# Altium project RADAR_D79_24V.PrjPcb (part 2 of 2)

## Sheet 23_Radar_bypass.SchDoc
size 289 x 400 mm
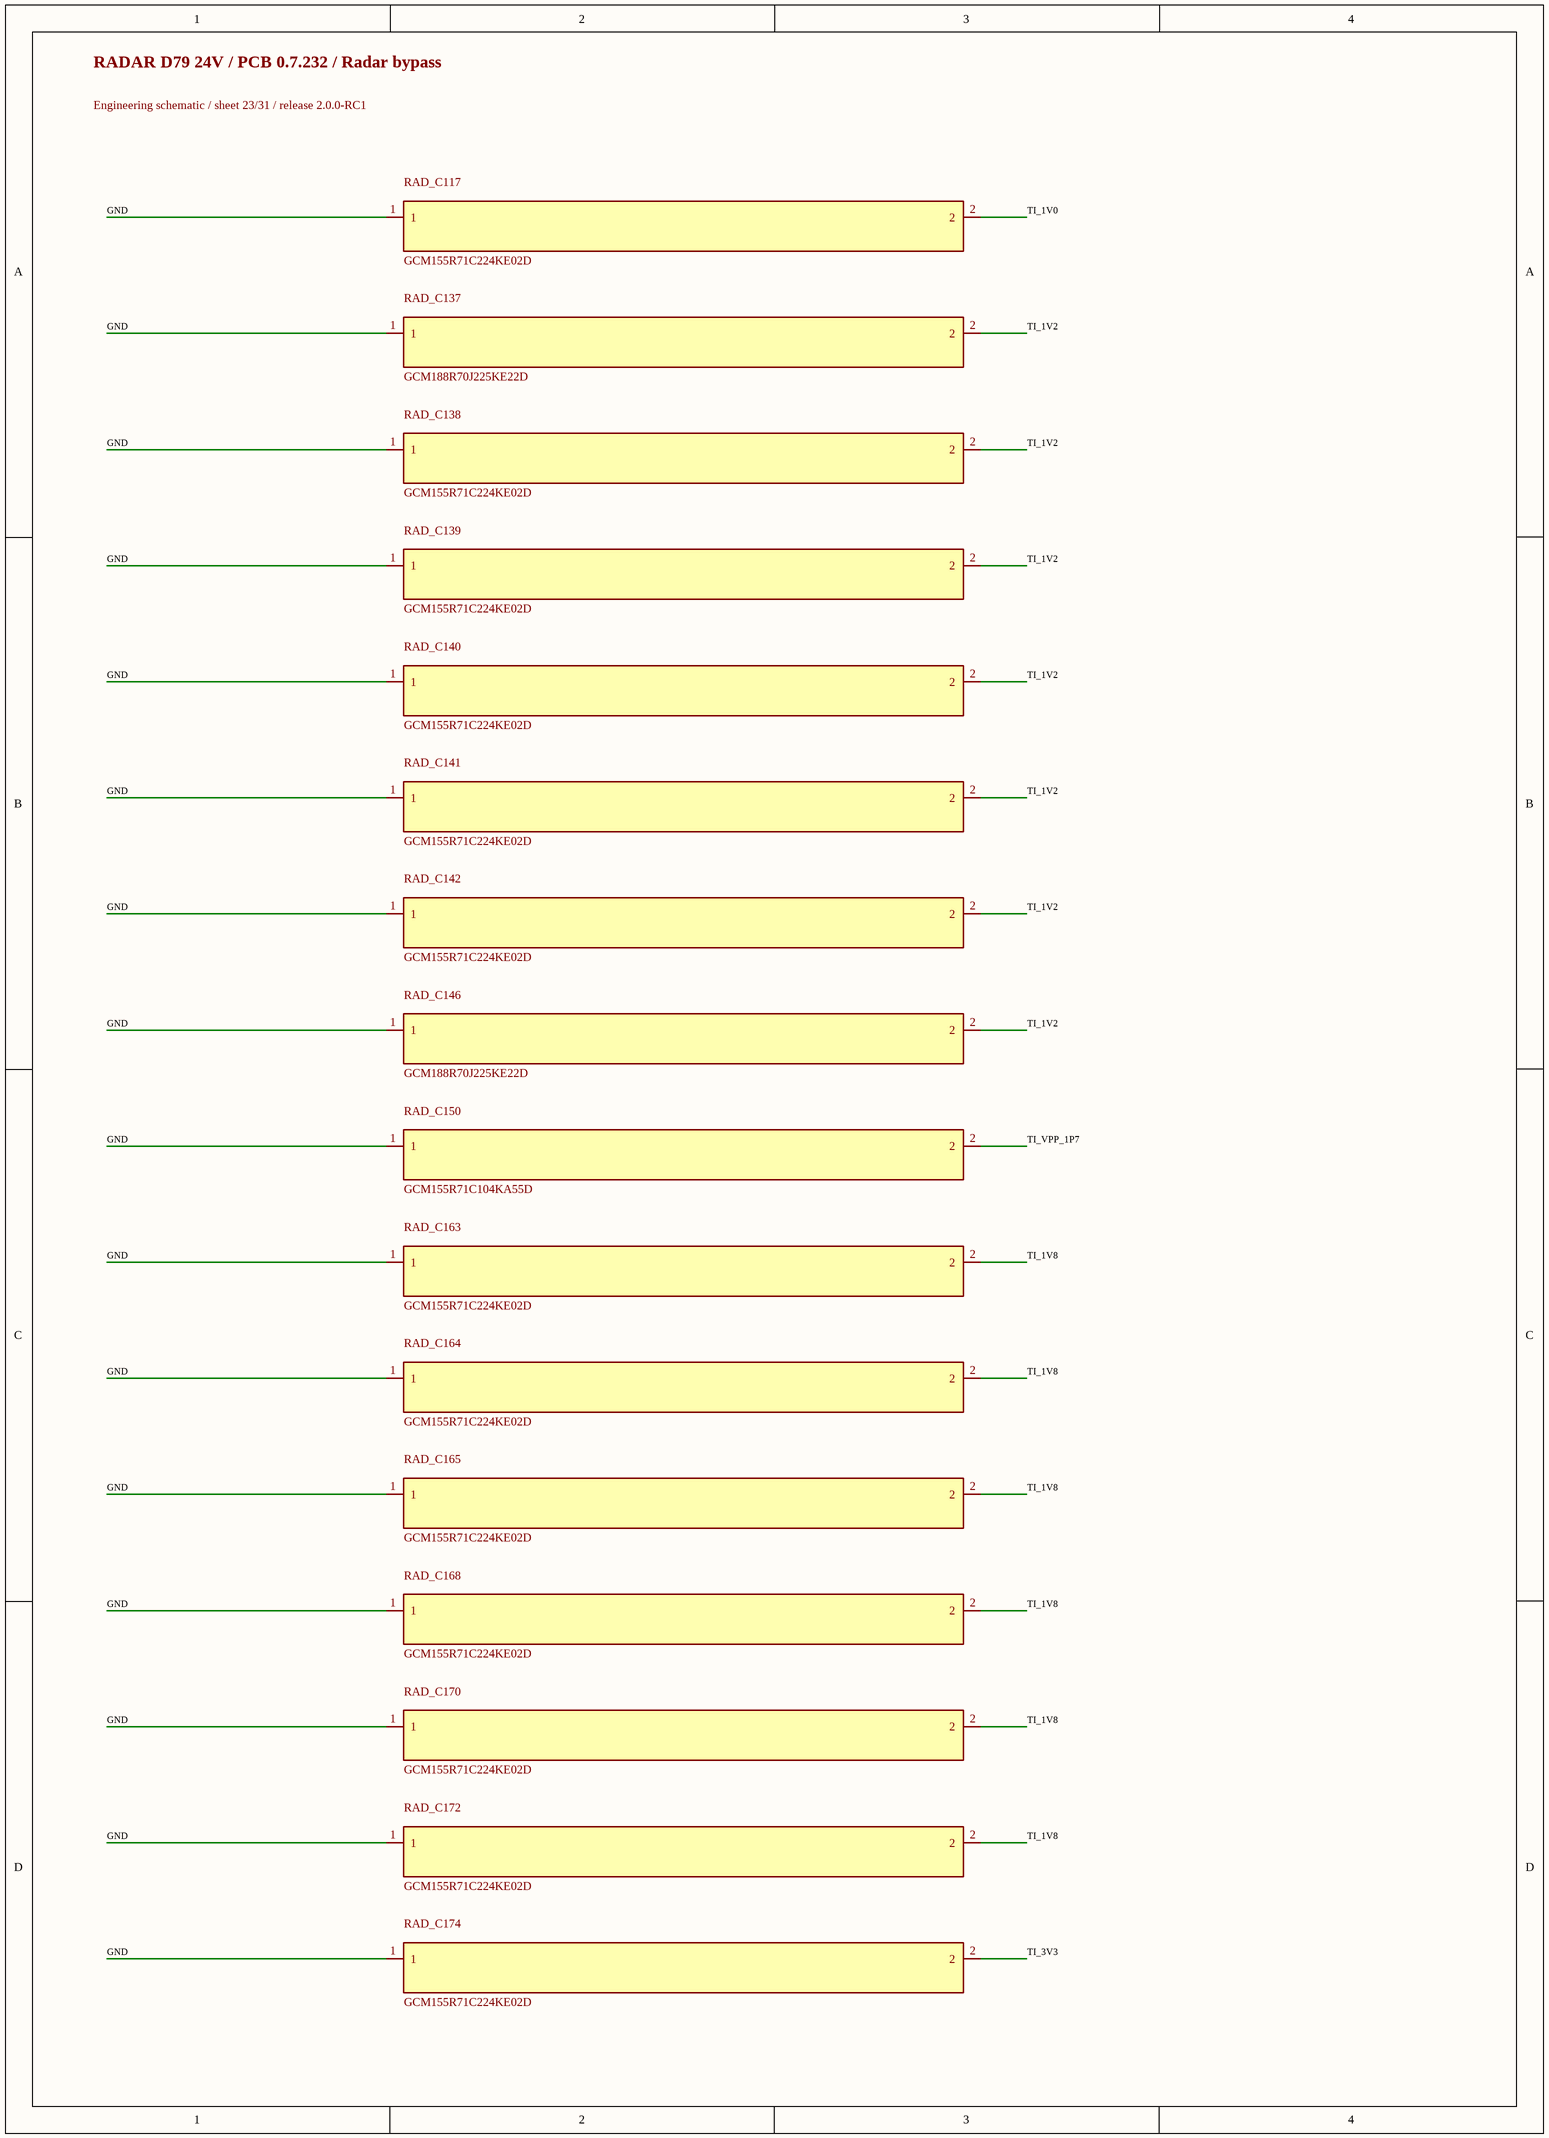
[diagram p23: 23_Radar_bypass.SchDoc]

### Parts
RAD_C117  GCM155R71C224KE02D  [0402L]
RAD_C137  GCM188R70J225KE22D  [0603L]
RAD_C138  GCM155R71C224KE02D  [0402L]
RAD_C139  GCM155R71C224KE02D  [0402L]
RAD_C140  GCM155R71C224KE02D  [0402L]
RAD_C141  GCM155R71C224KE02D  [0402L]
RAD_C142  GCM155R71C224KE02D  [0402L]
RAD_C146  GCM188R70J225KE22D  [0603L]
RAD_C150  GCM155R71C104KA55D  [0402L]
RAD_C163  GCM155R71C224KE02D  [0402L]
RAD_C164  GCM155R71C224KE02D  [0402L]
RAD_C165  GCM155R71C224KE02D  [0402L]
RAD_C168  GCM155R71C224KE02D  [0402L]
RAD_C170  GCM155R71C224KE02D  [0402L]
RAD_C172  GCM155R71C224KE02D  [0402L]
RAD_C174  GCM155R71C224KE02D  [0402L]

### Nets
GND: RAD_C117.1 RAD_C137.1 RAD_C138.1 RAD_C139.1 RAD_C140.1 RAD_C141.1 RAD_C142.1 RAD_C146.1 RAD_C150.1 RAD_C163.1 RAD_C164.1 RAD_C165.1 RAD_C168.1 RAD_C170.1 RAD_C172.1 RAD_C174.1
TI_1V0: RAD_C117.2
TI_1V2: RAD_C137.2 RAD_C138.2 RAD_C139.2 RAD_C140.2 RAD_C141.2 RAD_C142.2 RAD_C146.2
TI_1V8: RAD_C163.2 RAD_C164.2 RAD_C165.2 RAD_C168.2 RAD_C170.2 RAD_C172.2
TI_3V3: RAD_C174.2
TI_VPP_1P7: RAD_C150.2

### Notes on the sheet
- RADAR D79 24V / PCB 0.7.232 / Radar bypass
- Engineering schematic / sheet 23/31 / release 2.0.0-RC1

## Sheet 24_Radar_bypass.SchDoc
size 289 x 396 mm
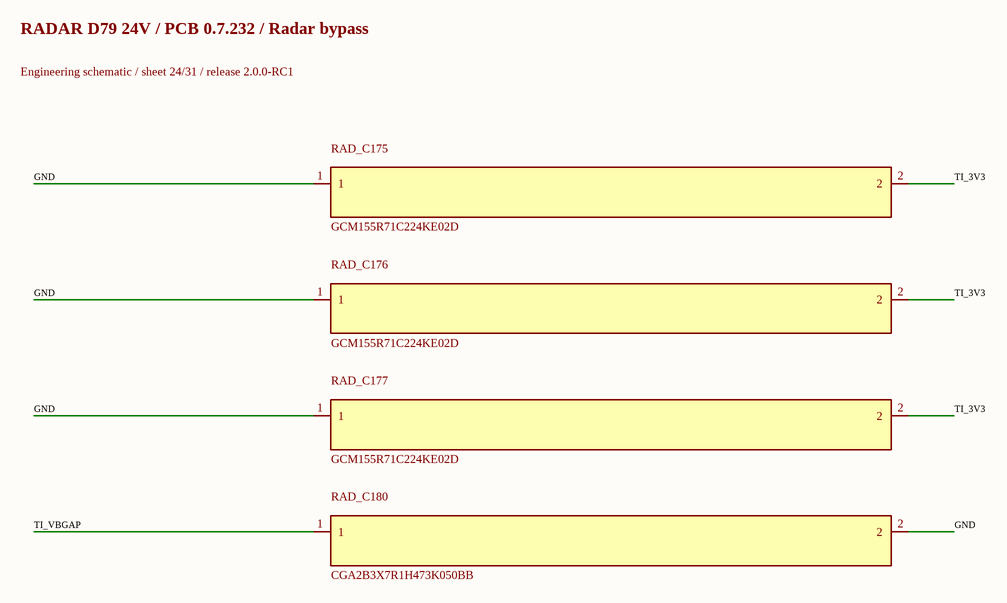
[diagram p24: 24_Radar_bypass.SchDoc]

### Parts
RAD_C175  GCM155R71C224KE02D  [0402L]
RAD_C176  GCM155R71C224KE02D  [0402L]
RAD_C177  GCM155R71C224KE02D  [0402L]
RAD_C180  CGA2B3X7R1H473K050BB  [0402L]

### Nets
GND: RAD_C175.1 RAD_C176.1 RAD_C177.1 RAD_C180.2
TI_3V3: RAD_C175.2 RAD_C176.2 RAD_C177.2
TI_VBGAP: RAD_C180.1

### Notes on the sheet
- RADAR D79 24V / PCB 0.7.232 / Radar bypass
- Engineering schematic / sheet 24/31 / release 2.0.0-RC1

## Sheet 25_Radar_PMIC_and_rail_filters.SchDoc
size 289 x 396 mm
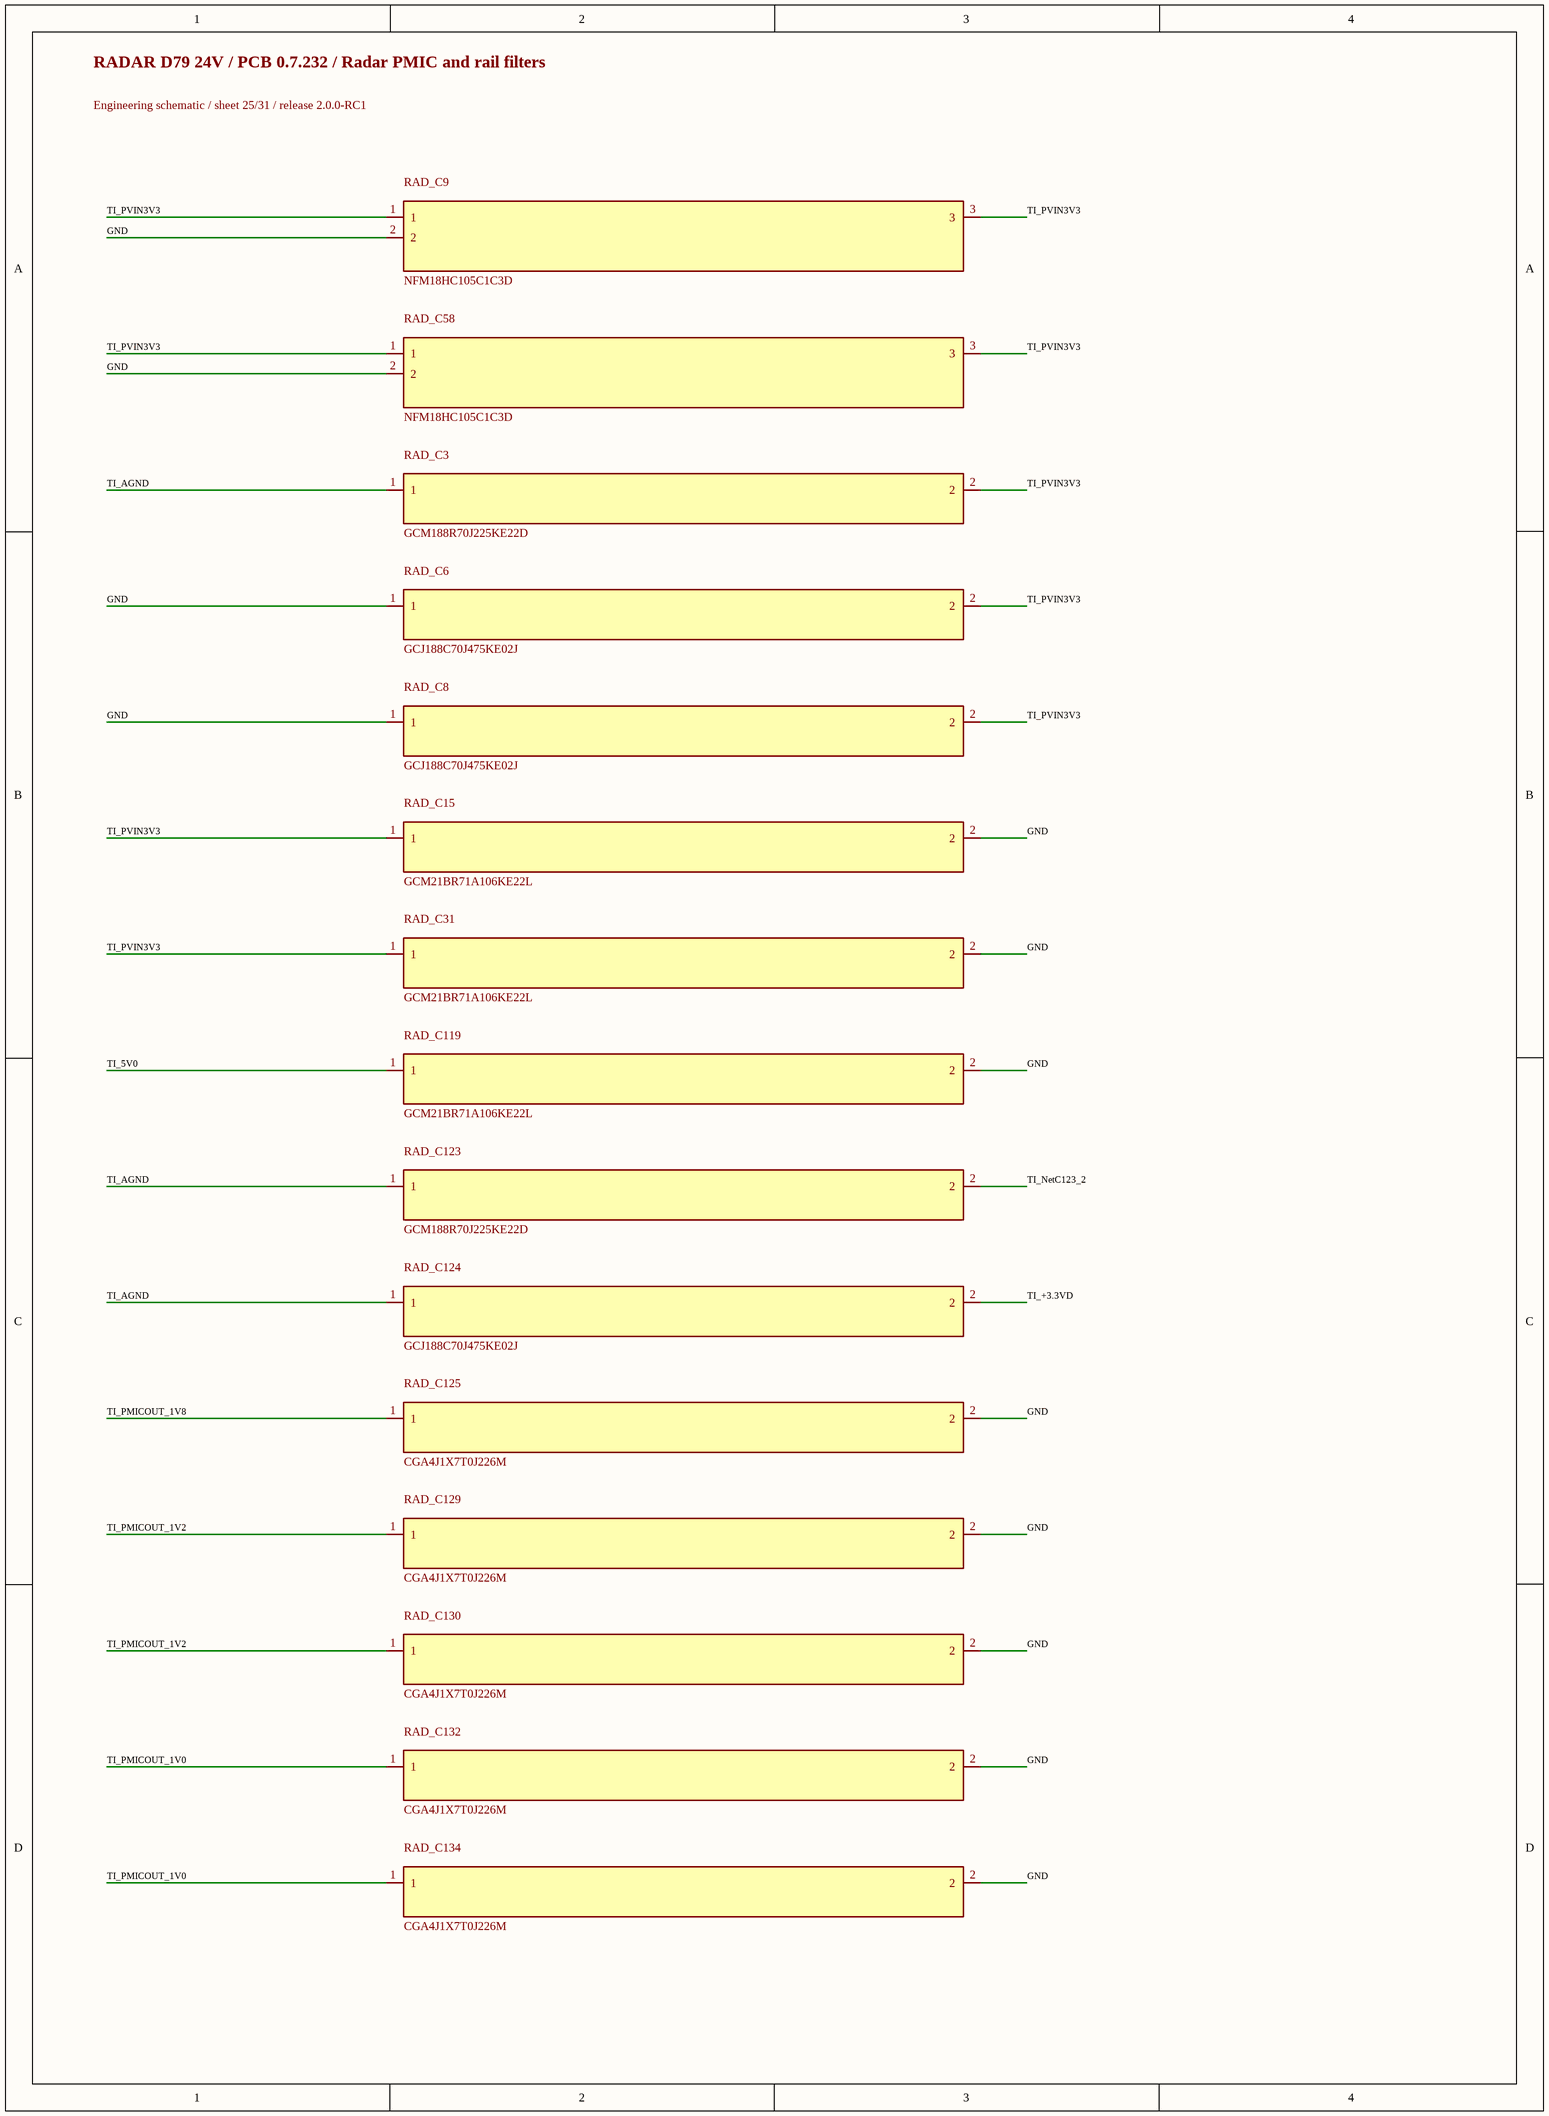
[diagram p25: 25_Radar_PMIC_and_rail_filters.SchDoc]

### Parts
RAD_C3  GCM188R70J225KE22D  [0603L]
RAD_C6  GCJ188C70J475KE02J  [FP-GCJ188C70J475KE02J_0603-MFG]
RAD_C8  GCJ188C70J475KE02J  [FP-GCJ188C70J475KE02J_0603-MFG]
RAD_C9  NFM18HC105C1C3D  [FP-NFM18HC105C1C3D_0603-MFG]
RAD_C15  GCM21BR71A106KE22L  [0805L]
RAD_C31  GCM21BR71A106KE22L  [0805L]
RAD_C58  NFM18HC105C1C3D  [FP-NFM18HC105C1C3D_0603-MFG]
RAD_C119  GCM21BR71A106KE22L  [0805L]
RAD_C123  GCM188R70J225KE22D  [0603L]
RAD_C124  GCJ188C70J475KE02J  [FP-GCJ188C70J475KE02J_0603-MFG]
RAD_C125  CGA4J1X7T0J226M  [0805_155]
RAD_C129  CGA4J1X7T0J226M  [0805_155]
RAD_C130  CGA4J1X7T0J226M  [0805_155]
RAD_C132  CGA4J1X7T0J226M  [0805_155]
RAD_C134  CGA4J1X7T0J226M  [0805_155]

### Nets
GND: RAD_C6.1 RAD_C8.1 RAD_C9.2 RAD_C15.2 RAD_C31.2 RAD_C58.2 RAD_C119.2 RAD_C125.2 RAD_C129.2 RAD_C130.2 RAD_C132.2 RAD_C134.2
TI_5V0: RAD_C119.1
TI_+3.3VD: RAD_C124.2
TI_AGND: RAD_C3.1 RAD_C123.1 RAD_C124.1
TI_NetC123_2: RAD_C123.2
TI_PMICOUT_1V0: RAD_C132.1 RAD_C134.1
TI_PMICOUT_1V2: RAD_C129.1 RAD_C130.1
TI_PMICOUT_1V8: RAD_C125.1
TI_PVIN3V3: RAD_C3.2 RAD_C6.2 RAD_C8.2 RAD_C9.1 RAD_C9.3 RAD_C15.1 RAD_C31.1 RAD_C58.1 RAD_C58.3

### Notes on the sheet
- RADAR D79 24V / PCB 0.7.232 / Radar PMIC and rail filters
- Engineering schematic / sheet 25/31 / release 2.0.0-RC1

## Sheet 26_Radar_PMIC_and_rail_filters.SchDoc
size 289 x 400 mm
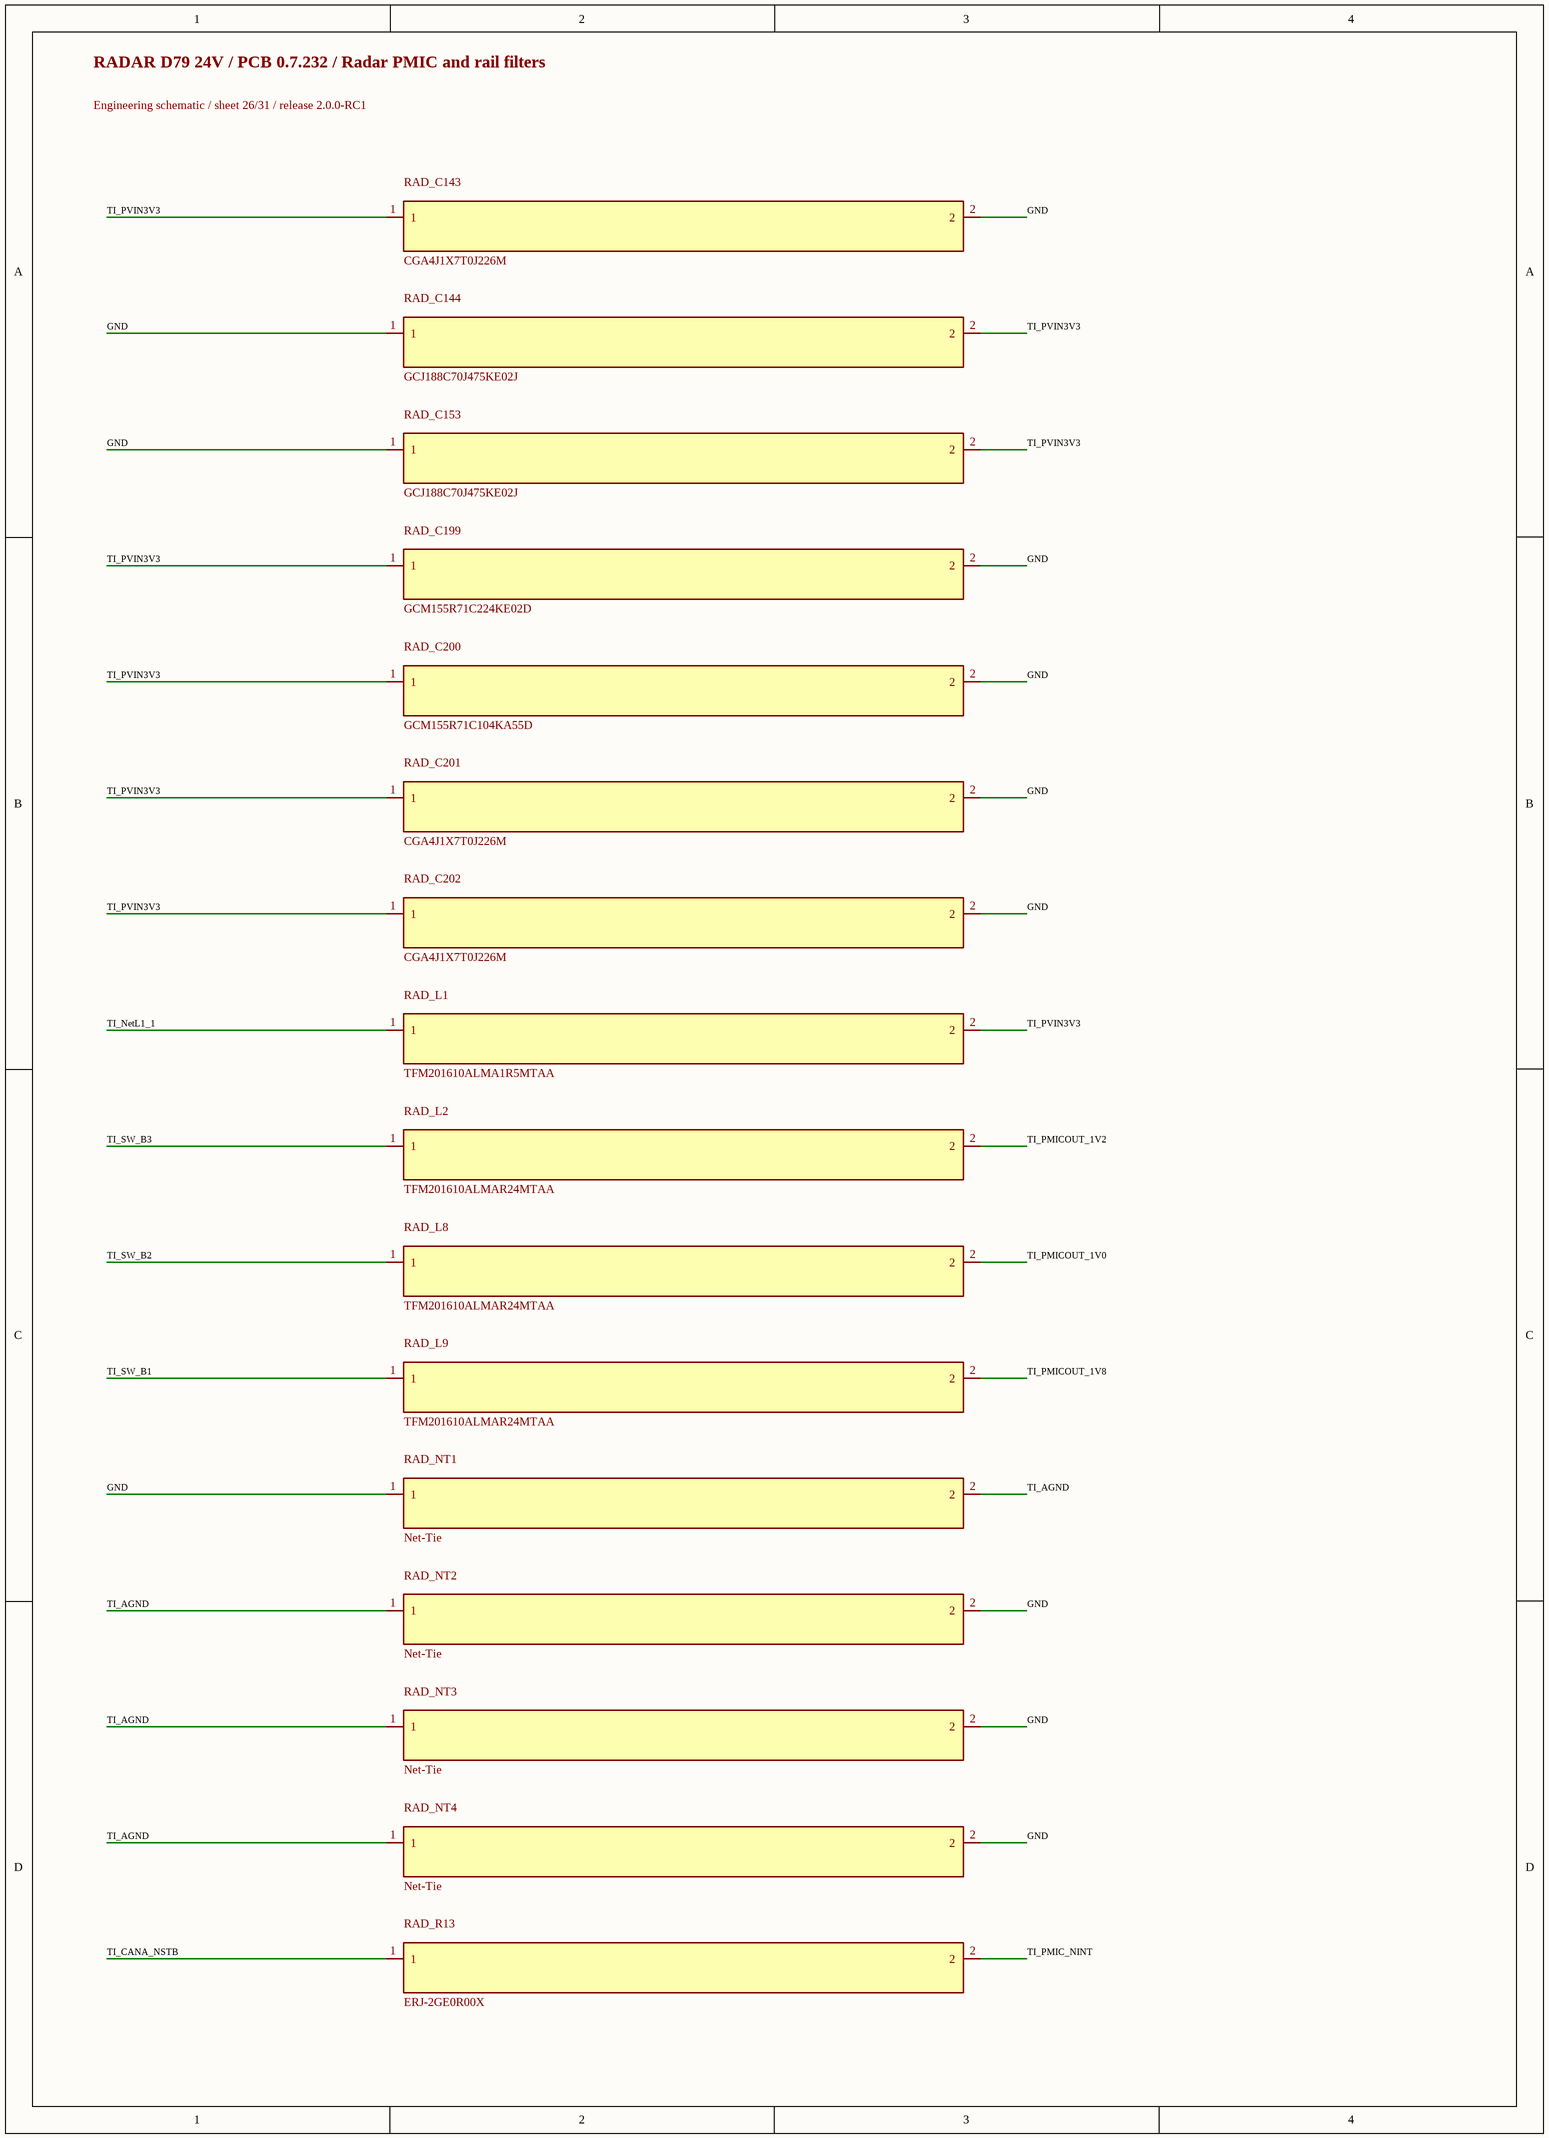
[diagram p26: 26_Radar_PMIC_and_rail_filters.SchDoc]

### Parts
RAD_C143  CGA4J1X7T0J226M  [0805_155]
RAD_C144  GCJ188C70J475KE02J  [FP-GCJ188C70J475KE02J_0603-MFG]
RAD_C153  GCJ188C70J475KE02J  [FP-GCJ188C70J475KE02J_0603-MFG]
RAD_C199  GCM155R71C224KE02D  [0402L]
RAD_C200  GCM155R71C104KA55D  [0402L]
RAD_C201  CGA4J1X7T0J226M  [0805_155]
RAD_C202  CGA4J1X7T0J226M  [0805_155]
RAD_L1  TFM201610ALMA1R5MTAA  [TFM201610ALMA]
RAD_L2  TFM201610ALMAR24MTAA  [FP-TFM201610ALMAR24MTAA_0806 (2016 Metric)-MFG]
RAD_L8  TFM201610ALMAR24MTAA  [FP-TFM201610ALMAR24MTAA_0806 (2016 Metric)-MFG]
RAD_L9  TFM201610ALMAR24MTAA  [FP-TFM201610ALMAR24MTAA_0806 (2016 Metric)-MFG]
RAD_NT1  Net-Tie  [Net-Tie_50milWide_30milLong]  (net tie, no BOM)
RAD_NT2  Net-Tie  [Net-Tie_50milWide_30milLong]  (net tie, no BOM)
RAD_NT3  Net-Tie  [Net-Tie_50milWide_30milLong]  (net tie, no BOM)
RAD_NT4  Net-Tie  [Net-Tie_50milWide_30milLong]  (net tie, no BOM)
RAD_R13  ERJ-2GE0R00X  [0402L]

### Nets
GND: RAD_C143.2 RAD_C144.1 RAD_C153.1 RAD_C199.2 RAD_C200.2 RAD_C201.2 RAD_C202.2 RAD_NT1.1 RAD_NT2.2 RAD_NT3.2 RAD_NT4.2
TI_AGND: RAD_NT1.2 RAD_NT2.1 RAD_NT3.1 RAD_NT4.1
TI_CANA_NSTB: RAD_R13.1
TI_NetL1_1: RAD_L1.1
TI_PMIC_NINT: RAD_R13.2
TI_PMICOUT_1V0: RAD_L8.2
TI_PMICOUT_1V2: RAD_L2.2
TI_PMICOUT_1V8: RAD_L9.2
TI_PVIN3V3: RAD_C143.1 RAD_C144.2 RAD_C153.2 RAD_C199.1 RAD_C200.1 RAD_C201.1 RAD_C202.1 RAD_L1.2
TI_SW_B1: RAD_L9.1
TI_SW_B2: RAD_L8.1
TI_SW_B3: RAD_L2.1

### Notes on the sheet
- RADAR D79 24V / PCB 0.7.232 / Radar PMIC and rail filters
- Engineering schematic / sheet 26/31 / release 2.0.0-RC1

## Sheet 27_Radar_PMIC_and_rail_filters.SchDoc
size 289 x 400 mm
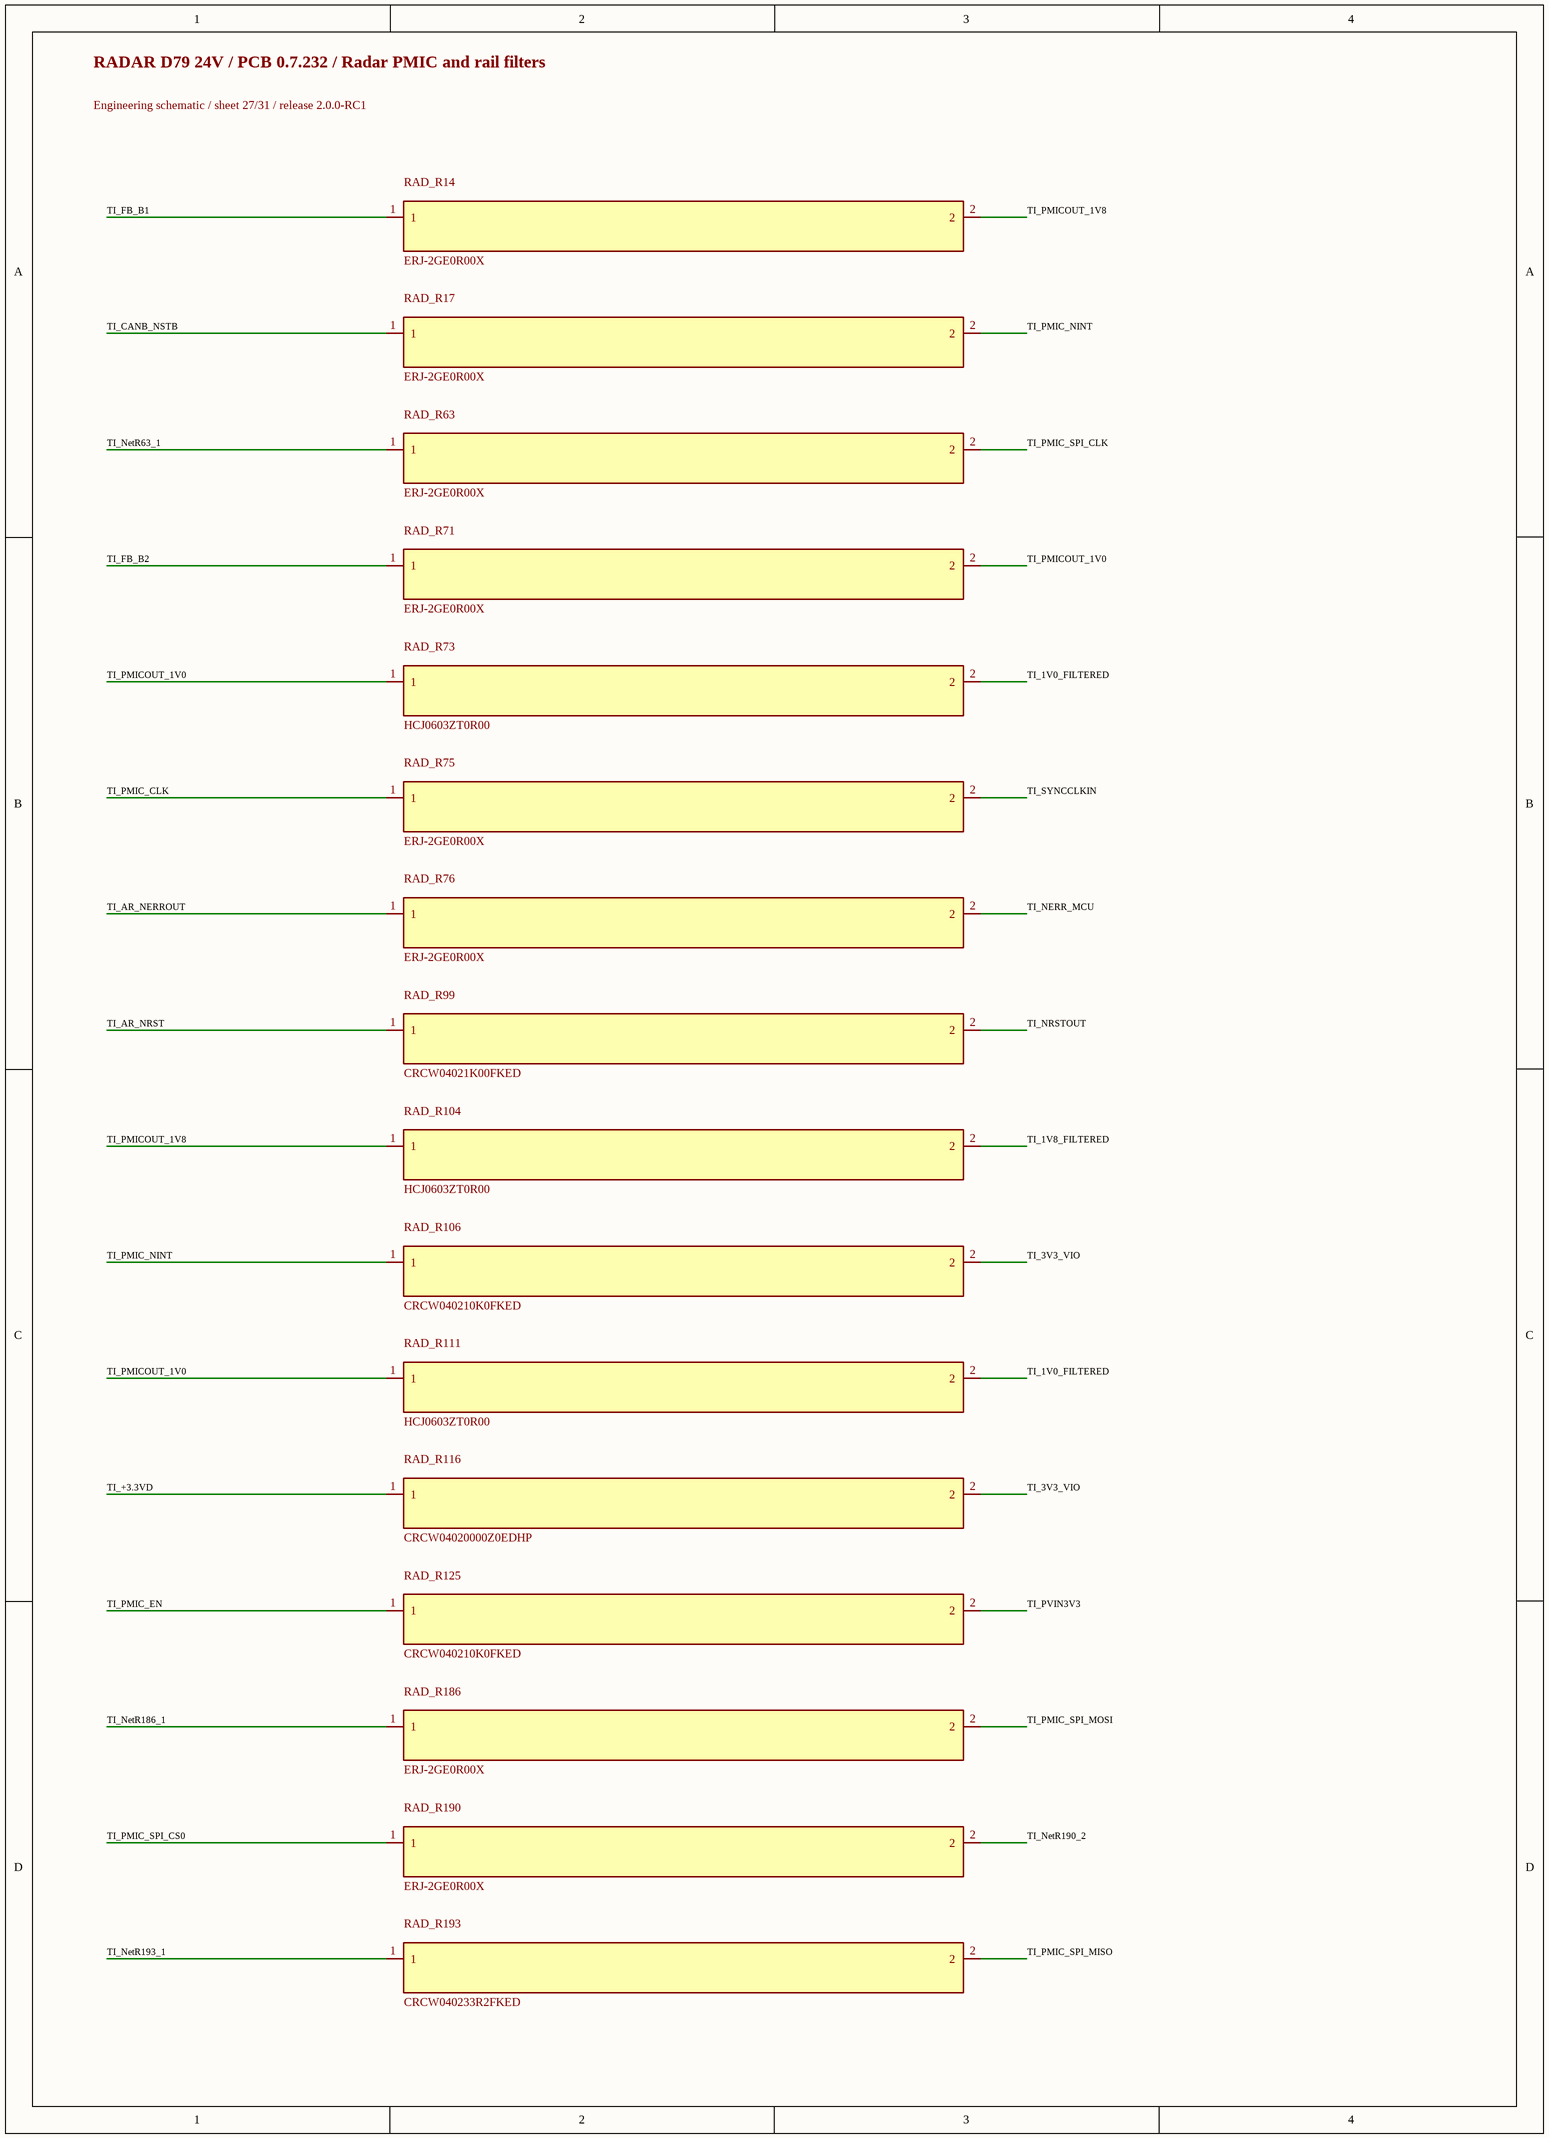
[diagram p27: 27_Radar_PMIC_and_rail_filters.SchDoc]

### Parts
RAD_R14  ERJ-2GE0R00X  [0402L]
RAD_R17  ERJ-2GE0R00X  [0402L]
RAD_R63  ERJ-2GE0R00X  [0402L]
RAD_R71  ERJ-2GE0R00X  [0402L]
RAD_R73  HCJ0603ZT0R00  [FP-HCJ0603ZT0R00_0603-MFG]
RAD_R75  ERJ-2GE0R00X  [0402L]
RAD_R76  ERJ-2GE0R00X  [0402L]
RAD_R99  CRCW04021K00FKED  [0402L]
RAD_R104  HCJ0603ZT0R00  [FP-HCJ0603ZT0R00_0603-MFG]
RAD_R106  CRCW040210K0FKED  [0402L]
RAD_R111  HCJ0603ZT0R00  [FP-HCJ0603ZT0R00_0603-MFG]
RAD_R116  CRCW04020000Z0EDHP  [0402L]
RAD_R125  CRCW040210K0FKED  [0402L]
RAD_R186  ERJ-2GE0R00X  [0402L]
RAD_R190  ERJ-2GE0R00X  [0402L]
RAD_R193  CRCW040233R2FKED  [0402L]

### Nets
TI_1V0_FILTERED: RAD_R73.2 RAD_R111.2
TI_1V8_FILTERED: RAD_R104.2
TI_3V3_VIO: RAD_R106.2 RAD_R116.2
TI_+3.3VD: RAD_R116.1
TI_AR_NERROUT: RAD_R76.1
TI_AR_NRST: RAD_R99.1
TI_CANB_NSTB: RAD_R17.1
TI_FB_B1: RAD_R14.1
TI_FB_B2: RAD_R71.1
TI_NERR_MCU: RAD_R76.2
TI_NetR63_1: RAD_R63.1
TI_NetR186_1: RAD_R186.1
TI_NetR190_2: RAD_R190.2
TI_NetR193_1: RAD_R193.1
TI_NRSTOUT: RAD_R99.2
TI_PMIC_CLK: RAD_R75.1
TI_PMIC_EN: RAD_R125.1
TI_PMIC_NINT: RAD_R17.2 RAD_R106.1
TI_PMIC_SPI_CLK: RAD_R63.2
TI_PMIC_SPI_CS0: RAD_R190.1
TI_PMIC_SPI_MISO: RAD_R193.2
TI_PMIC_SPI_MOSI: RAD_R186.2
TI_PMICOUT_1V0: RAD_R71.2 RAD_R73.1 RAD_R111.1
TI_PMICOUT_1V8: RAD_R14.2 RAD_R104.1
TI_PVIN3V3: RAD_R125.2
TI_SYNCCLKIN: RAD_R75.2

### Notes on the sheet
- RADAR D79 24V / PCB 0.7.232 / Radar PMIC and rail filters
- Engineering schematic / sheet 27/31 / release 2.0.0-RC1

## Sheet 28_Radar_PMIC_and_rail_filters.SchDoc
size 289 x 396 mm
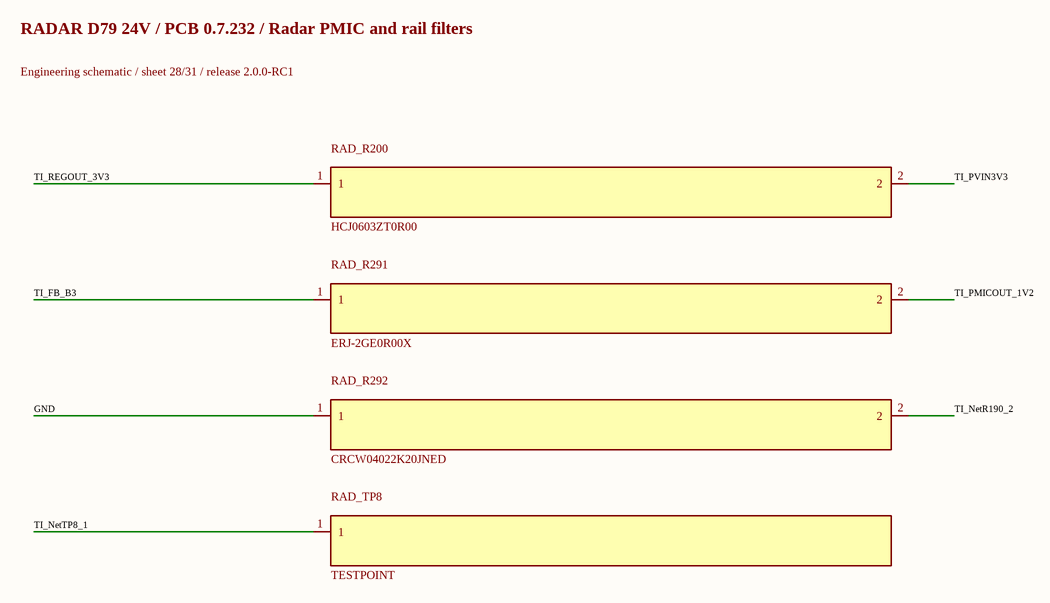
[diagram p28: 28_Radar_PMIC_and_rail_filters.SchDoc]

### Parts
RAD_R200  HCJ0603ZT0R00  [FP-HCJ0603ZT0R00_0603-MFG]
RAD_R291  ERJ-2GE0R00X  [0402L]
RAD_R292  CRCW04022K20JNED  [0402L]
RAD_TP8  TESTPOINT  [TP_25MIL-SMT]

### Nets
GND: RAD_R292.1
TI_FB_B3: RAD_R291.1
TI_NetR190_2: RAD_R292.2
TI_NetTP8_1: RAD_TP8.1
TI_PMICOUT_1V2: RAD_R291.2
TI_PVIN3V3: RAD_R200.2
TI_REGOUT_3V3: RAD_R200.1

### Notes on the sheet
- RADAR D79 24V / PCB 0.7.232 / Radar PMIC and rail filters
- Engineering schematic / sheet 28/31 / release 2.0.0-RC1

## Sheet 29_Radar_rail_selection_and_sensing.SchDoc
size 289 x 396 mm
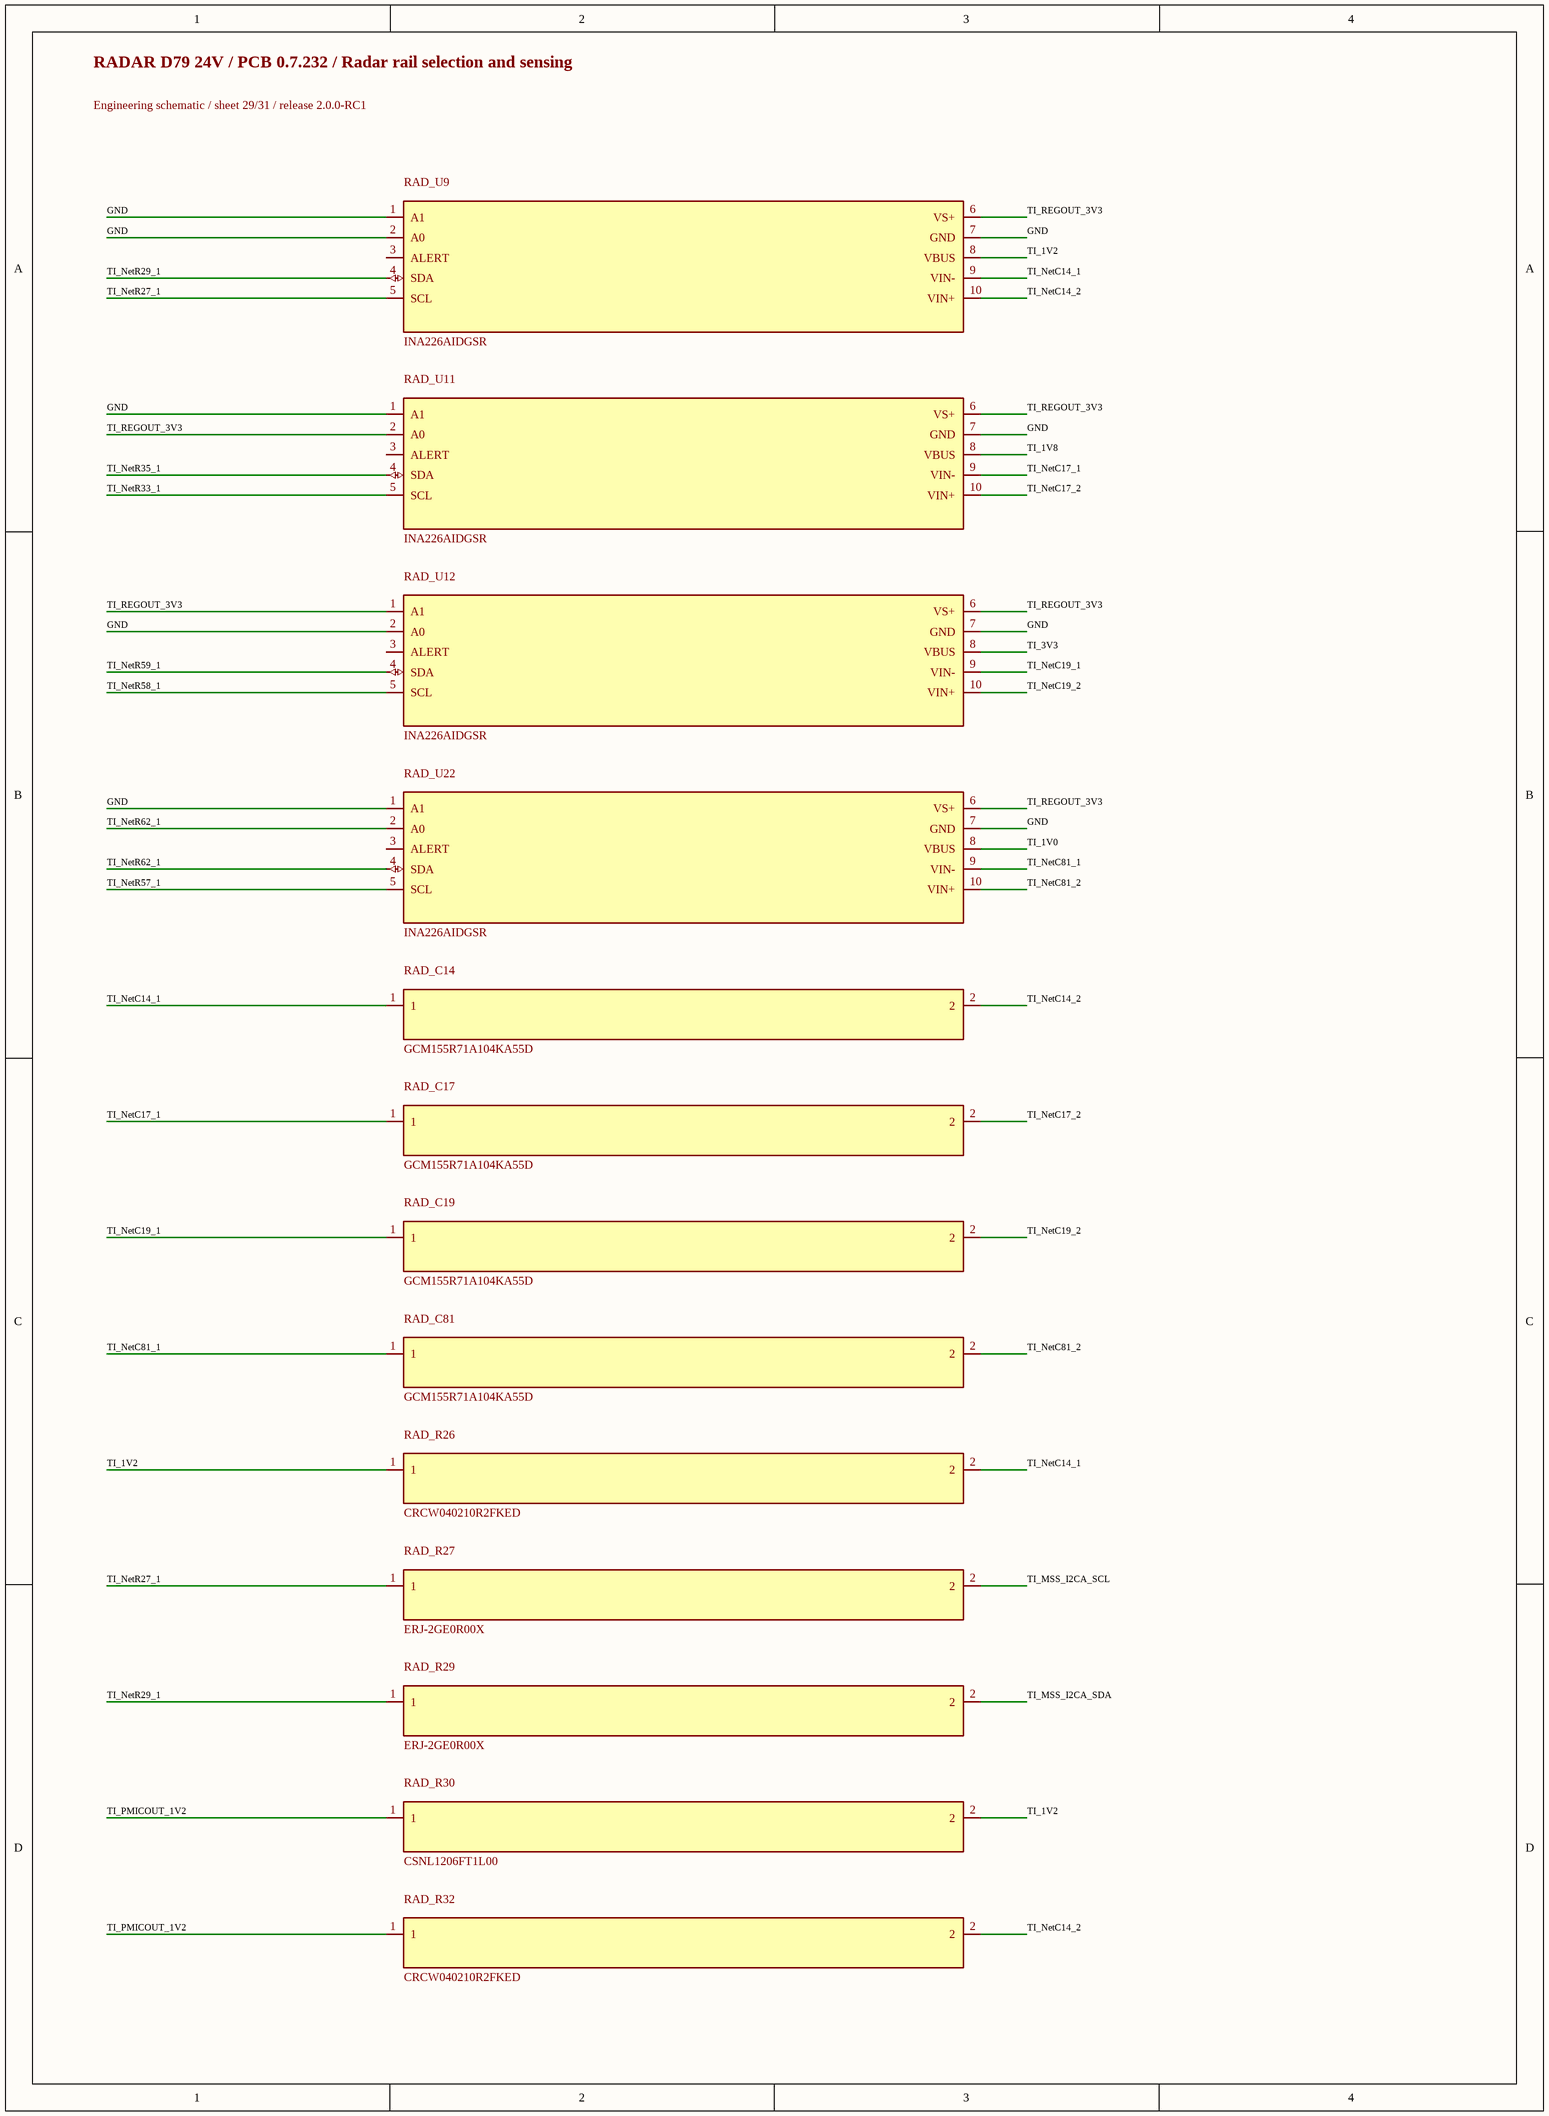
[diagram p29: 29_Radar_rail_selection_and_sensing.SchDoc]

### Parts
RAD_C14  GCM155R71A104KA55D  [0402L]
RAD_C17  GCM155R71A104KA55D  [0402L]
RAD_C19  GCM155R71A104KA55D  [0402L]
RAD_C81  GCM155R71A104KA55D  [0402L]
RAD_R26  CRCW040210R2FKED  [0402L]
RAD_R27  ERJ-2GE0R00X  [0402L]
RAD_R29  ERJ-2GE0R00X  [0402L]
RAD_R30  CSNL1206FT1L00  [1206L]
RAD_R32  CRCW040210R2FKED  [0402L]
RAD_U9  INA226AIDGSR  [DGS0010A_L]
RAD_U11  INA226AIDGSR  [DGS0010A_L]
RAD_U12  INA226AIDGSR  [DGS0010A_L]
RAD_U22  INA226AIDGSR  [DGS0010A_L]

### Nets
GND: RAD_U9.1(A1) RAD_U9.2(A0) RAD_U9.7(GND) RAD_U11.1(A1) RAD_U11.7(GND) RAD_U12.2(A0) RAD_U12.7(GND) RAD_U22.1(A1) RAD_U22.7(GND)
TI_1V0: RAD_U22.8(VBUS)
TI_1V2: RAD_R26.1 RAD_R30.2 RAD_U9.8(VBUS)
TI_1V8: RAD_U11.8(VBUS)
TI_3V3: RAD_U12.8(VBUS)
TI_MSS_I2CA_SCL: RAD_R27.2
TI_MSS_I2CA_SDA: RAD_R29.2
TI_NetC14_1: RAD_C14.1 RAD_R26.2 RAD_U9.9(VIN-)
TI_NetC14_2: RAD_C14.2 RAD_R32.2 RAD_U9.10(VIN+)
TI_NetC17_1: RAD_C17.1 RAD_U11.9(VIN-)
TI_NetC17_2: RAD_C17.2 RAD_U11.10(VIN+)
TI_NetC19_1: RAD_C19.1 RAD_U12.9(VIN-)
TI_NetC19_2: RAD_C19.2 RAD_U12.10(VIN+)
TI_NetC81_1: RAD_C81.1 RAD_U22.9(VIN-)
TI_NetC81_2: RAD_C81.2 RAD_U22.10(VIN+)
TI_NetR27_1: RAD_R27.1 RAD_U9.5(SCL)
TI_NetR29_1: RAD_R29.1 RAD_U9.4(SDA)
TI_NetR33_1: RAD_U11.5(SCL)
TI_NetR35_1: RAD_U11.4(SDA)
TI_NetR57_1: RAD_U22.5(SCL)
TI_NetR58_1: RAD_U12.5(SCL)
TI_NetR59_1: RAD_U12.4(SDA)
TI_NetR62_1: RAD_U22.2(A0) RAD_U22.4(SDA)
TI_PMICOUT_1V2: RAD_R30.1 RAD_R32.1
TI_REGOUT_3V3: RAD_U9.6(VS+) RAD_U11.2(A0) RAD_U11.6(VS+) RAD_U12.1(A1) RAD_U12.6(VS+) RAD_U22.6(VS+)

Not connected (* = marked no-connect by the designer): RAD_U9 3(ALERT); RAD_U11 3(ALERT); RAD_U12 3(ALERT); RAD_U22 3(ALERT)

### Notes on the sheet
- RADAR D79 24V / PCB 0.7.232 / Radar rail selection and sensing
- Engineering schematic / sheet 29/31 / release 2.0.0-RC1

## Sheet 30_Radar_rail_selection_and_sensing.SchDoc
size 289 x 396 mm
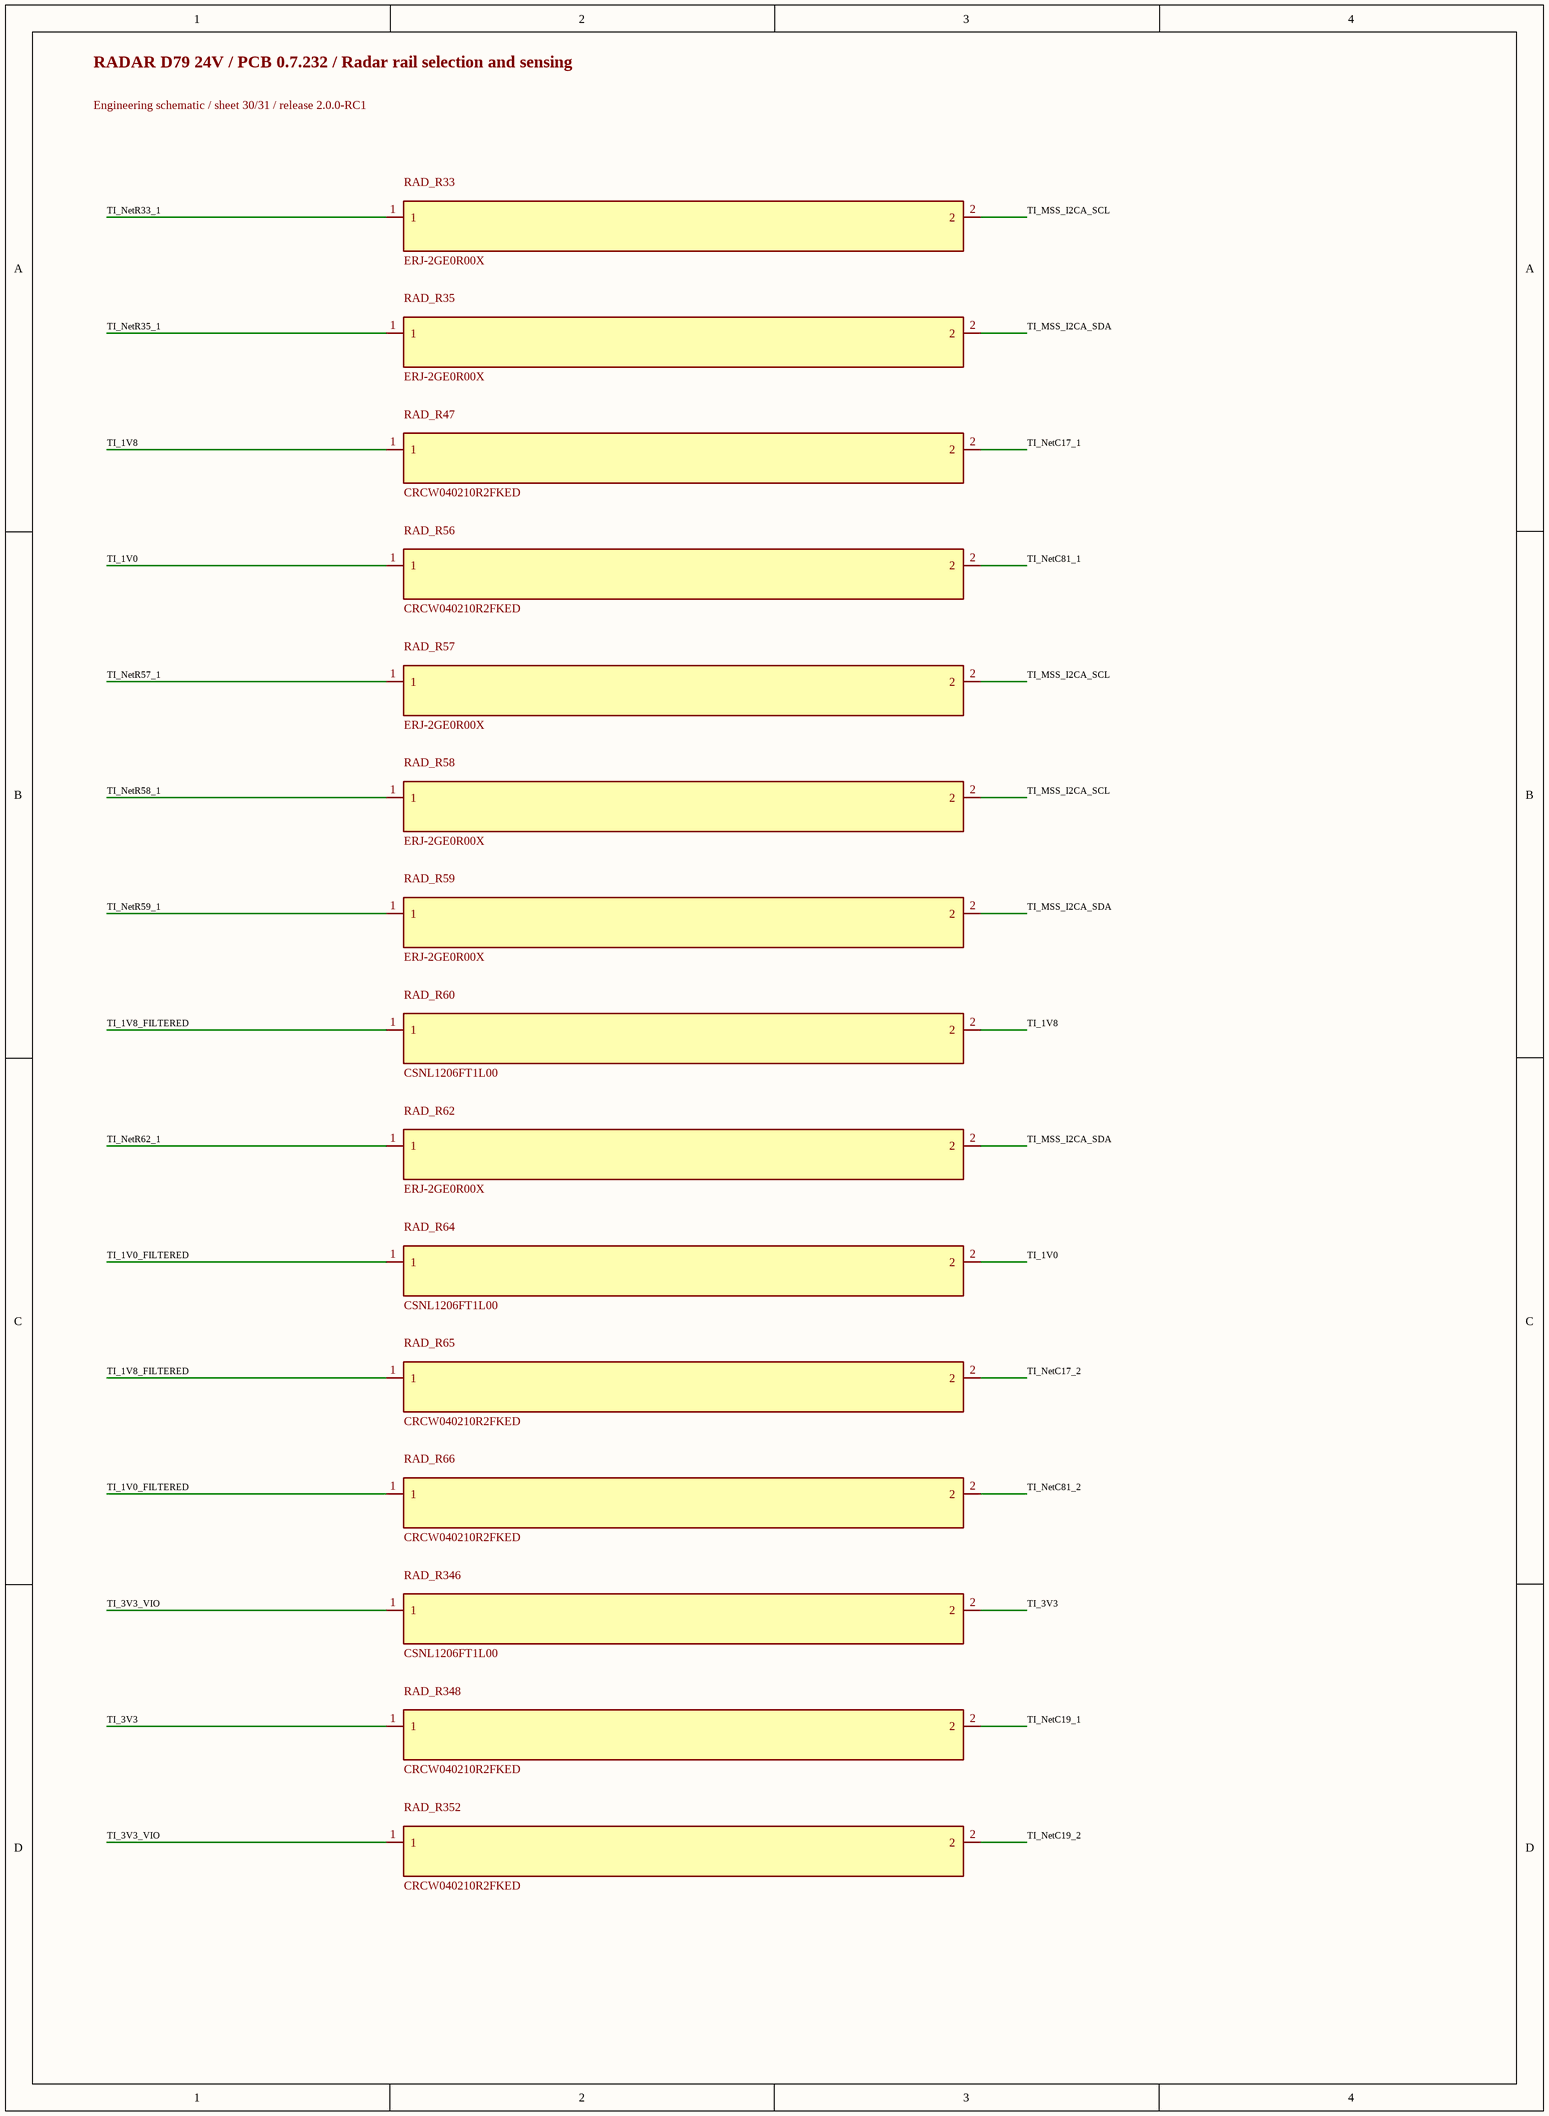
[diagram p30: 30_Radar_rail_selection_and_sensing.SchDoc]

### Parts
RAD_R33  ERJ-2GE0R00X  [0402L]
RAD_R35  ERJ-2GE0R00X  [0402L]
RAD_R47  CRCW040210R2FKED  [0402L]
RAD_R56  CRCW040210R2FKED  [0402L]
RAD_R57  ERJ-2GE0R00X  [0402L]
RAD_R58  ERJ-2GE0R00X  [0402L]
RAD_R59  ERJ-2GE0R00X  [0402L]
RAD_R60  CSNL1206FT1L00  [1206L]
RAD_R62  ERJ-2GE0R00X  [0402L]
RAD_R64  CSNL1206FT1L00  [1206L]
RAD_R65  CRCW040210R2FKED  [0402L]
RAD_R66  CRCW040210R2FKED  [0402L]
RAD_R346  CSNL1206FT1L00  [1206L]
RAD_R348  CRCW040210R2FKED  [0402L]
RAD_R352  CRCW040210R2FKED  [0402L]

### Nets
TI_1V0: RAD_R56.1 RAD_R64.2
TI_1V0_FILTERED: RAD_R64.1 RAD_R66.1
TI_1V8: RAD_R47.1 RAD_R60.2
TI_1V8_FILTERED: RAD_R60.1 RAD_R65.1
TI_3V3: RAD_R346.2 RAD_R348.1
TI_3V3_VIO: RAD_R346.1 RAD_R352.1
TI_MSS_I2CA_SCL: RAD_R33.2 RAD_R57.2 RAD_R58.2
TI_MSS_I2CA_SDA: RAD_R35.2 RAD_R59.2 RAD_R62.2
TI_NetC17_1: RAD_R47.2
TI_NetC17_2: RAD_R65.2
TI_NetC19_1: RAD_R348.2
TI_NetC19_2: RAD_R352.2
TI_NetC81_1: RAD_R56.2
TI_NetC81_2: RAD_R66.2
TI_NetR33_1: RAD_R33.1
TI_NetR35_1: RAD_R35.1
TI_NetR57_1: RAD_R57.1
TI_NetR58_1: RAD_R58.1
TI_NetR59_1: RAD_R59.1
TI_NetR62_1: RAD_R62.1

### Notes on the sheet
- RADAR D79 24V / PCB 0.7.232 / Radar rail selection and sensing
- Engineering schematic / sheet 30/31 / release 2.0.0-RC1

## Sheet 31_Radar_VPP_service.SchDoc
size 289 x 396 mm
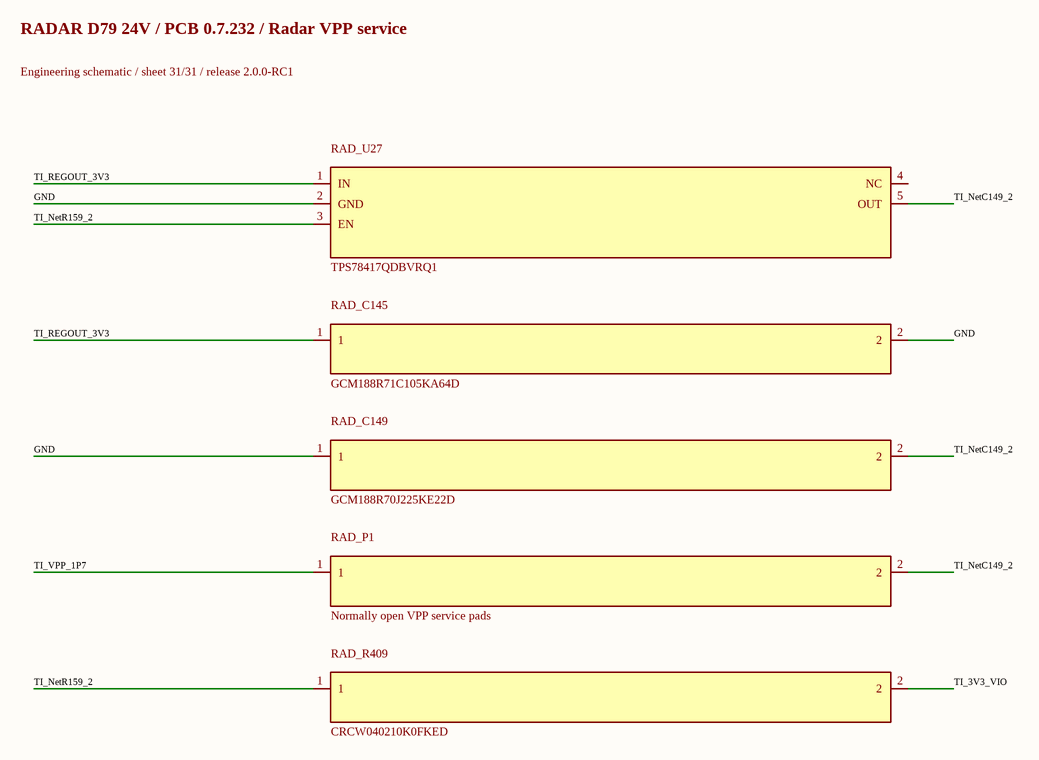
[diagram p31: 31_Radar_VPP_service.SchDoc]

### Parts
RAD_C145  GCM188R71C105KA64D  [0603L]
RAD_C149  GCM188R70J225KE22D  [0603L]
RAD_P1  Normally open VPP service pads  [VPP_SERVICE_SMT_D1p5_P2p5]
RAD_R409  CRCW040210K0FKED  [0402L]
RAD_U27  TPS78417QDBVRQ1  [DBV0005A-MFG]

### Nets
GND: RAD_C145.2 RAD_C149.1 RAD_U27.2(GND)
TI_3V3_VIO: RAD_R409.2
TI_NetC149_2: RAD_C149.2 RAD_P1.2 RAD_U27.5(OUT)
TI_NetR159_2: RAD_R409.1 RAD_U27.3(EN)
TI_REGOUT_3V3: RAD_C145.1 RAD_U27.1(IN)
TI_VPP_1P7: RAD_P1.1

Not connected (* = marked no-connect by the designer): RAD_U27 4(NC)

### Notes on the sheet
- RADAR D79 24V / PCB 0.7.232 / Radar VPP service
- Engineering schematic / sheet 31/31 / release 2.0.0-RC1

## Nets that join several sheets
3V3: 01_10_POWER_INPUT (U5.14), 02_10_POWER_INPUT (C2.1), 03_10_POWER_INPUT (L1.2 R5P.2 R6F.2 R7F.2), 04_10_POWER_INPUT (R803.2), 05_60_HOST_UART (R600.1 R605.1), 06_50_RADAR_IO_CAN (C40.1 U4.3), 07_70_DEBUG_BOOT (R70.2), 09_20_MCU_CORE (17 pins), 10_20_MCU_CORE (11 pins), 11_20_MCU_CORE (9 pins), 12_40_IMU (5 pins), 14_Radar_interfaces_and_QSPI (C_FRAME.1 U_FRAME.5)
5V_GNSS: 01_10_POWER_INPUT (U9.14), 02_10_POWER_INPUT (C91.1), 03_10_POWER_INPUT (L9.2), 04_10_POWER_INPUT (R90.2), 08_30_TIME_GNSS (J8.1)
BOOT0: 07_70_DEBUG_BOOT (R70.1), 09_20_MCU_CORE (U1.166), 11_20_MCU_CORE (R10.1)
BUCK5_SW: 01_10_POWER_INPUT (U9.1 U9.2 U9.3), 03_10_POWER_INPUT (L9.1)
BUCK_SW: 01_10_POWER_INPUT (U5.1 U5.2 U5.3), 03_10_POWER_INPUT (L1.1)
CAN_RX: 06_50_RADAR_IO_CAN (U4.4), 09_20_MCU_CORE (U1.142)
CAN_TX: 06_50_RADAR_IO_CAN (U4.1), 09_20_MCU_CORE (U1.143)
GND: 01_10_POWER_INPUT (28 pins), 02_10_POWER_INPUT (14 pins), 03_10_POWER_INPUT (9 pins), 04_10_POWER_INPUT (5 pins), 05_60_HOST_UART (D3.3 D3.8 J6.1 J6.4), 06_50_RADAR_IO_CAN (6 pins), 07_70_DEBUG_BOOT (SW1.2), 08_30_TIME_GNSS (D8.3 D8.8 J8.6), 09_20_MCU_CORE (13 pins), 10_20_MCU_CORE (16 pins), 11_20_MCU_CORE (10 pins), 12_40_IMU (6 pins), 13_Radar_interfaces_and_QSPI (120 pins), 14_Radar_interfaces_and_QSPI (15 pins), 15_Radar_interfaces_and_QSPI (R_CAN_SHDN.2 R_CAN_STB.2 R_FRAME_PD.2), 16_Radar_service_USB_and_boot (14 pins), 17_Radar_service_USB_and_boot (5 pins), 18_Radar_service_USB_and_boot (TP_RAD_GND.1), 19_Radar_12V_to_3V3 (13 pins), 21_Radar_input_and_reference (6 pins), 22_Radar_bypass (15 pins), 23_Radar_bypass (16 pins), 24_Radar_bypass (RAD_C175.1 RAD_C176.1 RAD_C177.1 RAD_C180.2), 25_Radar_PMIC_and_rail_filters (12 pins), 26_Radar_PMIC_and_rail_filters (11 pins), 28_Radar_PMIC_and_rail_filters (RAD_R292.1), 29_Radar_rail_selection_and_sensing (9 pins), 31_Radar_VPP_service (RAD_C145.2 RAD_C149.1 RAD_U27.2)
GNSS_PPS: 08_30_TIME_GNSS (D8.4 J8.4), 09_20_MCU_CORE (U1.40)
GNSS_RX_EXT: 08_30_TIME_GNSS (D8.1 J8.2), 09_20_MCU_CORE (U1.96)
GNSS_TX_EXT: 08_30_TIME_GNSS (D8.2 J8.3), 09_20_MCU_CORE (U1.97)
HOST_UART1_RX: 05_60_HOST_UART (R600.2 R602.2), 09_20_MCU_CORE (U1.150), 11_20_MCU_CORE (TP2.1)
HOST_UART1_TX: 05_60_HOST_UART (R601.2), 09_20_MCU_CORE (U1.147), 11_20_MCU_CORE (TP1.1)
HOST_UART2_RX: 05_60_HOST_UART (R604.2 R605.2), 09_20_MCU_CORE (U1.121)
HOST_UART2_TX: 05_60_HOST_UART (R603.2), 09_20_MCU_CORE (U1.120)
IMU_DRDY: 09_20_MCU_CORE (U1.80), 12_40_IMU (U2.4)
IMU_MISO: 09_20_MCU_CORE (U1.94), 12_40_IMU (U2.1)
IMU_MOSI: 09_20_MCU_CORE (U1.95), 12_40_IMU (U2.14)
IMU_NSS: 09_20_MCU_CORE (U1.92), 12_40_IMU (U2.12)
IMU_SCK: 09_20_MCU_CORE (U1.93), 12_40_IMU (U2.13)
MCU_HSE_25M: 09_20_MCU_CORE (U1.29), 10_20_MCU_CORE (Y1.3)
NRST: 07_70_DEBUG_BOOT (SW1.1), 09_20_MCU_CORE (U1.31), 11_20_MCU_CORE (C115.1)
RAD_CAN_SHDN: 14_Radar_interfaces_and_QSPI (U_CAN_RAD.5), 15_Radar_interfaces_and_QSPI (R_CAN_SHDN.1)
RAD_CAN_STB: 14_Radar_interfaces_and_QSPI (U_CAN_RAD.8), 15_Radar_interfaces_and_QSPI (R_CAN_STB.1)
RAD_FRAME_RAW: 13_Radar_interfaces_and_QSPI (RAD_U29.G15), 14_Radar_interfaces_and_QSPI (U_FRAME.2), 15_Radar_interfaces_and_QSPI (R_FRAME_PD.1)
RADAR_12V: 01_10_POWER_INPUT (U7.6), 19_Radar_12V_to_3V3 (5 pins), 21_Radar_input_and_reference (RAD_C99.1 RAD_C101.1 RAD_L5.2)
RADAR_CANH: 06_50_RADAR_IO_CAN (D4.1 R40.1 U4.7), 14_Radar_interfaces_and_QSPI (U_CAN_RAD.7), 15_Radar_interfaces_and_QSPI (R_CAN_TERM.1)
RADAR_CANL: 06_50_RADAR_IO_CAN (D4.2 R40.2 U4.6), 14_Radar_interfaces_and_QSPI (U_CAN_RAD.6), 15_Radar_interfaces_and_QSPI (R_CAN_TERM.2)
RADAR_EFUSE_FLT: 01_10_POWER_INPUT (U7.4), 03_10_POWER_INPUT (R7F.1), 09_20_MCU_CORE (U1.2)
RADAR_REF: 09_20_MCU_CORE (U1.79), 14_Radar_interfaces_and_QSPI (U_FRAME.4)
SWCLK: 09_20_MCU_CORE (U1.137), 10_20_MCU_CORE (J10.4)
SWDIO: 09_20_MCU_CORE (U1.124), 10_20_MCU_CORE (J10.2)
SWO: 09_20_MCU_CORE (U1.161), 10_20_MCU_CORE (J10.6)
SYS_EFUSE_FLT: 01_10_POWER_INPUT (U6.14), 03_10_POWER_INPUT (R6F.1), 09_20_MCU_CORE (U1.1)
TI_1V0: 13_Radar_interfaces_and_QSPI (RAD_U29.D6 RAD_U29.D7 RAD_U29.M4), 22_Radar_bypass (7 pins), 23_Radar_bypass (RAD_C117.2), 29_Radar_rail_selection_and_sensing (RAD_U22.8), 30_Radar_rail_selection_and_sensing (RAD_R56.1 RAD_R64.2)
TI_1V0_FILTERED: 27_Radar_PMIC_and_rail_filters (RAD_R73.2 RAD_R111.2), 30_Radar_rail_selection_and_sensing (RAD_R64.1 RAD_R66.1)
TI_1V2: 13_Radar_interfaces_and_QSPI (19 pins), 22_Radar_bypass (RAD_C92.2 RAD_C96.2), 23_Radar_bypass (7 pins), 29_Radar_rail_selection_and_sensing (RAD_R26.1 RAD_R30.2 RAD_U9.8)
TI_1V4_APLL: 13_Radar_interfaces_and_QSPI (RAD_U29.H4), 22_Radar_bypass (RAD_C103.1)
TI_1V4_SYNTH: 13_Radar_interfaces_and_QSPI (RAD_U29.G4), 22_Radar_bypass (RAD_C102.1)
TI_1V8: 13_Radar_interfaces_and_QSPI (9 pins), 22_Radar_bypass (6 pins), 23_Radar_bypass (6 pins), 29_Radar_rail_selection_and_sensing (RAD_U11.8), 30_Radar_rail_selection_and_sensing (RAD_R47.1 RAD_R60.2)
TI_1V8_FILTERED: 27_Radar_PMIC_and_rail_filters (RAD_R104.2), 30_Radar_rail_selection_and_sensing (RAD_R60.1 RAD_R65.1)
TI_3V3: 13_Radar_interfaces_and_QSPI (5 pins), 23_Radar_bypass (RAD_C174.2), 24_Radar_bypass (RAD_C175.2 RAD_C176.2 RAD_C177.2), 29_Radar_rail_selection_and_sensing (RAD_U12.8), 30_Radar_rail_selection_and_sensing (RAD_R346.2 RAD_R348.1)
TI_3V3_VIO: 14_Radar_interfaces_and_QSPI (C_CAN_RAD.1 U_CAN_RAD.3), 15_Radar_interfaces_and_QSPI (5 pins), 16_Radar_service_USB_and_boot (6 pins), 17_Radar_service_USB_and_boot (5 pins), 18_Radar_service_USB_and_boot (TP_RAD_VIO.1), 21_Radar_input_and_reference (RAD_R276.2 RAD_R277.2), 27_Radar_PMIC_and_rail_filters (RAD_R106.2 RAD_R116.2), 30_Radar_rail_selection_and_sensing (RAD_R346.1 RAD_R352.1), 31_Radar_VPP_service (RAD_R409.2)
TI_3V3REG_MODE: 19_Radar_12V_to_3V3 (RAD_U2.6), 20_Radar_12V_to_3V3 (RAD_R9.1)
TI_3V3REG_VCC: 19_Radar_12V_to_3V3 (RAD_C10.1 RAD_U2.3), 20_Radar_12V_to_3V3 (RAD_R9.2)
TI_5V0: 14_Radar_interfaces_and_QSPI (RAD_U8.10), 25_Radar_PMIC_and_rail_filters (RAD_C119.1)
TI_+3.3VD: 14_Radar_interfaces_and_QSPI (RAD_U8.9), 25_Radar_PMIC_and_rail_filters (RAD_C124.2), 27_Radar_PMIC_and_rail_filters (RAD_R116.1)
TI_AGND: 14_Radar_interfaces_and_QSPI (RAD_U8.5 RAD_U8.5-19 RAD_U8.19), 25_Radar_PMIC_and_rail_filters (RAD_C3.1 RAD_C123.1 RAD_C124.1), 26_Radar_PMIC_and_rail_filters (RAD_NT1.2 RAD_NT2.1 RAD_NT3.1 RAD_NT4.1)
TI_AR_NERROUT: 13_Radar_interfaces_and_QSPI (RAD_U29.C11), 27_Radar_PMIC_and_rail_filters (RAD_R76.1)
TI_AR_NRST: 13_Radar_interfaces_and_QSPI (RAD_U29.H16), 16_Radar_service_USB_and_boot (RAD_C105.2 RAD_R264.1), 18_Radar_service_USB_and_boot (TP_RAD_RESET.1), 27_Radar_PMIC_and_rail_filters (RAD_R99.1)
TI_FB_B1: 14_Radar_interfaces_and_QSPI (RAD_U8.3), 27_Radar_PMIC_and_rail_filters (RAD_R14.1)
TI_FB_B2: 14_Radar_interfaces_and_QSPI (RAD_U8.21), 27_Radar_PMIC_and_rail_filters (RAD_R71.1)
TI_FB_B3: 14_Radar_interfaces_and_QSPI (RAD_U8.17), 28_Radar_PMIC_and_rail_filters (RAD_R291.1)
TI_MSS_I2CA_SCL: 21_Radar_input_and_reference (RAD_R276.1), 29_Radar_rail_selection_and_sensing (RAD_R27.2), 30_Radar_rail_selection_and_sensing (RAD_R33.2 RAD_R57.2 RAD_R58.2)
TI_MSS_I2CA_SDA: 21_Radar_input_and_reference (RAD_R277.1), 29_Radar_rail_selection_and_sensing (RAD_R29.2), 30_Radar_rail_selection_and_sensing (RAD_R35.2 RAD_R59.2 RAD_R62.2)
TI_MSS_MCANA_RX: 13_Radar_interfaces_and_QSPI (RAD_U29.D16), 14_Radar_interfaces_and_QSPI (U_CAN_RAD.4)
TI_MSS_MCANA_TX: 13_Radar_interfaces_and_QSPI (RAD_U29.D17), 14_Radar_interfaces_and_QSPI (U_CAN_RAD.1)
TI_MSS_UARTA_RX: 13_Radar_interfaces_and_QSPI (RAD_U29.B16), 16_Radar_service_USB_and_boot (RAD_R129.1)
TI_NERR_MCU: 14_Radar_interfaces_and_QSPI (RAD_U8.16), 27_Radar_PMIC_and_rail_filters (RAD_R76.2)
TI_NetC1_2: 14_Radar_interfaces_and_QSPI (RAD_C1.2 RAD_C2.2 RAD_U1.8), 15_Radar_interfaces_and_QSPI (RAD_R37.2)
TI_NetC17_1: 29_Radar_rail_selection_and_sensing (RAD_C17.1 RAD_U11.9), 30_Radar_rail_selection_and_sensing (RAD_R47.2)
TI_NetC17_2: 29_Radar_rail_selection_and_sensing (RAD_C17.2 RAD_U11.10), 30_Radar_rail_selection_and_sensing (RAD_R65.2)
TI_NetC19_1: 29_Radar_rail_selection_and_sensing (RAD_C19.1 RAD_U12.9), 30_Radar_rail_selection_and_sensing (RAD_R348.2)
TI_NetC19_2: 29_Radar_rail_selection_and_sensing (RAD_C19.2 RAD_U12.10), 30_Radar_rail_selection_and_sensing (RAD_R352.2)
TI_NetC81_1: 29_Radar_rail_selection_and_sensing (RAD_C81.1 RAD_U22.9), 30_Radar_rail_selection_and_sensing (RAD_R56.2)
TI_NetC81_2: 29_Radar_rail_selection_and_sensing (RAD_C81.2 RAD_U22.10), 30_Radar_rail_selection_and_sensing (RAD_R66.2)
TI_NetC123_2: 14_Radar_interfaces_and_QSPI (RAD_U8.18), 25_Radar_PMIC_and_rail_filters (RAD_C123.2)
TI_NetL1_1: 14_Radar_interfaces_and_QSPI (RAD_U8.11), 26_Radar_PMIC_and_rail_filters (RAD_L1.1)
TI_NetR33_1: 29_Radar_rail_selection_and_sensing (RAD_U11.5), 30_Radar_rail_selection_and_sensing (RAD_R33.1)
TI_NetR35_1: 29_Radar_rail_selection_and_sensing (RAD_U11.4), 30_Radar_rail_selection_and_sensing (RAD_R35.1)
TI_NetR57_1: 29_Radar_rail_selection_and_sensing (RAD_U22.5), 30_Radar_rail_selection_and_sensing (RAD_R57.1)
TI_NetR58_1: 29_Radar_rail_selection_and_sensing (RAD_U12.5), 30_Radar_rail_selection_and_sensing (RAD_R58.1)
TI_NetR59_1: 29_Radar_rail_selection_and_sensing (RAD_U12.4), 30_Radar_rail_selection_and_sensing (RAD_R59.1)
TI_NetR62_1: 29_Radar_rail_selection_and_sensing (RAD_U22.2 RAD_U22.4), 30_Radar_rail_selection_and_sensing (RAD_R62.1)
TI_NetR63_1: 14_Radar_interfaces_and_QSPI (RAD_U8.1), 27_Radar_PMIC_and_rail_filters (RAD_R63.1)
TI_NetR186_1: 14_Radar_interfaces_and_QSPI (RAD_U8.8), 27_Radar_PMIC_and_rail_filters (RAD_R186.1)
TI_NetR190_2: 14_Radar_interfaces_and_QSPI (RAD_U8.4), 27_Radar_PMIC_and_rail_filters (RAD_R190.2), 28_Radar_PMIC_and_rail_filters (RAD_R292.2)
TI_NetR193_1: 14_Radar_interfaces_and_QSPI (RAD_U8.2), 27_Radar_PMIC_and_rail_filters (RAD_R193.1)
TI_NetR298_1: 16_Radar_service_USB_and_boot (RAD_R299.2), 17_Radar_service_USB_and_boot (RAD_R300.1 RAD_R302.2)
TI_NetR386_2: 13_Radar_interfaces_and_QSPI (RAD_U29.D15), 17_Radar_service_USB_and_boot (RAD_R386.2)
TI_NetTP8_1: 14_Radar_interfaces_and_QSPI (RAD_U8.22), 28_Radar_PMIC_and_rail_filters (RAD_TP8.1)
TI_NRSTOUT: 14_Radar_interfaces_and_QSPI (RAD_U8.6), 27_Radar_PMIC_and_rail_filters (RAD_R99.2)
TI_PMIC_CLK_OUT: 13_Radar_interfaces_and_QSPI (RAD_U29.T17), 16_Radar_service_USB_and_boot (RAD_R218.1)
TI_PMIC_EN: 14_Radar_interfaces_and_QSPI (RAD_U8.15), 27_Radar_PMIC_and_rail_filters (RAD_R125.1)
TI_PMIC_NINT: 14_Radar_interfaces_and_QSPI (RAD_U8.7), 26_Radar_PMIC_and_rail_filters (RAD_R13.2), 27_Radar_PMIC_and_rail_filters (RAD_R17.2 RAD_R106.1)
TI_PMICOUT_1V0: 25_Radar_PMIC_and_rail_filters (RAD_C132.1 RAD_C134.1), 26_Radar_PMIC_and_rail_filters (RAD_L8.2), 27_Radar_PMIC_and_rail_filters (RAD_R71.2 RAD_R73.1 RAD_R111.1)
TI_PMICOUT_1V2: 25_Radar_PMIC_and_rail_filters (RAD_C129.1 RAD_C130.1), 26_Radar_PMIC_and_rail_filters (RAD_L2.2), 28_Radar_PMIC_and_rail_filters (RAD_R291.2), 29_Radar_rail_selection_and_sensing (RAD_R30.1 RAD_R32.1)
TI_PMICOUT_1V8: 21_Radar_input_and_reference (RAD_C60.1), 25_Radar_PMIC_and_rail_filters (RAD_C125.1), 26_Radar_PMIC_and_rail_filters (RAD_L9.2), 27_Radar_PMIC_and_rail_filters (RAD_R14.2 RAD_R104.1)
TI_PVIN3V3: 14_Radar_interfaces_and_QSPI (RAD_U8.13 RAD_U8.20 RAD_U8.25 RAD_U8.27), 25_Radar_PMIC_and_rail_filters (9 pins), 26_Radar_PMIC_and_rail_filters (8 pins), 27_Radar_PMIC_and_rail_filters (RAD_R125.2), 28_Radar_PMIC_and_rail_filters (RAD_R200.2)
TI_QSPI_CS: 13_Radar_interfaces_and_QSPI (RAD_U29.U12), 14_Radar_interfaces_and_QSPI (RAD_U1.1), 15_Radar_interfaces_and_QSPI (RAD_R38.1)
TI_QSPI_D0: 13_Radar_interfaces_and_QSPI (RAD_U29.U11), 15_Radar_interfaces_and_QSPI (RAD_R45.2)
TI_QSPI_D0_FLASH: 14_Radar_interfaces_and_QSPI (RAD_U1.5), 15_Radar_interfaces_and_QSPI (RAD_R45.1)
TI_QSPI_D1: 13_Radar_interfaces_and_QSPI (RAD_U29.V11), 15_Radar_interfaces_and_QSPI (RAD_R39.1 RAD_R49.1)
TI_QSPI_D1_FLASH: 14_Radar_interfaces_and_QSPI (RAD_U1.2), 15_Radar_interfaces_and_QSPI (RAD_R39.2)
TI_QSPI_D2: 13_Radar_interfaces_and_QSPI (RAD_U29.T11), 15_Radar_interfaces_and_QSPI (RAD_R42.1 RAD_R43.1)
TI_QSPI_D2_FLASH: 14_Radar_interfaces_and_QSPI (RAD_U1.3), 15_Radar_interfaces_and_QSPI (RAD_R42.2)
TI_QSPI_D3: 13_Radar_interfaces_and_QSPI (RAD_U29.R12), 15_Radar_interfaces_and_QSPI (RAD_R40.2 RAD_R41.1)
TI_QSPI_D3_FLASH: 14_Radar_interfaces_and_QSPI (RAD_U1.7), 15_Radar_interfaces_and_QSPI (RAD_R40.1)
TI_QSPI_SCLK: 13_Radar_interfaces_and_QSPI (RAD_U29.R10), 15_Radar_interfaces_and_QSPI (RAD_R44.2)
TI_QSPI_SCLK_FLASH: 14_Radar_interfaces_and_QSPI (RAD_U1.6), 15_Radar_interfaces_and_QSPI (RAD_R44.1)
TI_REGOUT_3V3: 19_Radar_12V_to_3V3 (7 pins), 28_Radar_PMIC_and_rail_filters (RAD_R200.1), 29_Radar_rail_selection_and_sensing (6 pins), 31_Radar_VPP_service (RAD_C145.1 RAD_U27.1)
TI_SOP1_MSS_SPIB_CS2: 13_Radar_interfaces_and_QSPI (RAD_U29.R14), 17_Radar_service_USB_and_boot (RAD_R305.1)
TI_SOP3_MSS_UARTB_TX: 13_Radar_interfaces_and_QSPI (RAD_U29.A14), 17_Radar_service_USB_and_boot (RAD_R301.1)
TI_SOP4_MSS_UARTA_TX: 13_Radar_interfaces_and_QSPI (RAD_U29.C16), 16_Radar_service_USB_and_boot (RAD_R128.1), 17_Radar_service_USB_and_boot (RAD_R309.1)
TI_SW_B1: 14_Radar_interfaces_and_QSPI (RAD_U8.28), 26_Radar_PMIC_and_rail_filters (RAD_L9.1)
TI_SW_B2: 14_Radar_interfaces_and_QSPI (RAD_U8.24), 26_Radar_PMIC_and_rail_filters (RAD_L8.1)
TI_SW_B3: 14_Radar_interfaces_and_QSPI (RAD_U8.14), 26_Radar_PMIC_and_rail_filters (RAD_L2.1)
TI_SYNCCLKIN: 14_Radar_interfaces_and_QSPI (RAD_U8.23), 27_Radar_PMIC_and_rail_filters (RAD_R75.2)
TI_VBGAP: 13_Radar_interfaces_and_QSPI (RAD_U29.K4), 24_Radar_bypass (RAD_C180.1)
TI_VPP_1P7: 13_Radar_interfaces_and_QSPI (RAD_U29.U3), 23_Radar_bypass (RAD_C150.2), 31_Radar_VPP_service (RAD_P1.1)
TI_XTALM: 13_Radar_interfaces_and_QSPI (RAD_U29.B1), 14_Radar_interfaces_and_QSPI (RAD_C108.1 RAD_Y3.3)
TI_XTALP: 13_Radar_interfaces_and_QSPI (RAD_U29.D1), 14_Radar_interfaces_and_QSPI (RAD_C106.1 RAD_Y3.1)
U5_PG: 01_10_POWER_INPUT (U5.4), 03_10_POWER_INPUT (R5P.1)
U5_SS_LOCAL: 01_10_POWER_INPUT (U5.9), 02_10_POWER_INPUT (C3.1)
U6_BGATE: 01_10_POWER_INPUT (Q6.4 U6.3), 02_10_POWER_INPUT (Q7.3)
U6_DRV: 01_10_POWER_INPUT (U6.4), 02_10_POWER_INPUT (Q7.1)
U6_DVDT: 01_10_POWER_INPUT (U6.9), 02_10_POWER_INPUT (C6D.1)
U6_ILIM_LOCAL: 01_10_POWER_INPUT (U6.10), 03_10_POWER_INPUT (R1.1)
U6_OVP_LOCAL: 01_10_POWER_INPUT (U6.7), 04_10_POWER_INPUT (R62.2 R63.1)
U6_PGTH_LOCAL: 01_10_POWER_INPUT (U6.15), 04_10_POWER_INPUT (R804.2 R805.1)
U6_UVLO_LOCAL: 01_10_POWER_INPUT (U6.6), 04_10_POWER_INPUT (R61.2 R62.1)
U7_DVDT: 01_10_POWER_INPUT (U7.7), 02_10_POWER_INPUT (C7D.1)
U7_ILIM_LOCAL: 01_10_POWER_INPUT (U7.9), 03_10_POWER_INPUT (R2.1)
U7_OVLO_LOCAL: 01_10_POWER_INPUT (U7.2), 04_10_POWER_INPUT (R72.2 R73.1)
U7_UVLO_LOCAL: 01_10_POWER_INPUT (U7.1), 04_10_POWER_INPUT (R71.2 R72.1)
U8_BOOT: 01_10_POWER_INPUT (U8.6), 03_10_POWER_INPUT (C805.1)
U8_ENABLE: 01_10_POWER_INPUT (U6.16 U8.18), 04_10_POWER_INPUT (R806.1)
U8_FB_LOCAL: 01_10_POWER_INPUT (U8.12), 04_10_POWER_INPUT (R800.2 R801.1)
U8_PGOOD: 01_10_POWER_INPUT (U8.16), 04_10_POWER_INPUT (R803.1)
U8_RT_LOCAL: 01_10_POWER_INPUT (U8.10), 04_10_POWER_INPUT (R802.1)
U8_SW: 01_10_POWER_INPUT (5 pins), 03_10_POWER_INPUT (C805.2 L8.1)
U8_VCC: 01_10_POWER_INPUT (U8.8), 03_10_POWER_INPUT (C803.1)
U9_PG: 01_10_POWER_INPUT (U9.4), 04_10_POWER_INPUT (R90.1)
U9_SS_LOCAL: 01_10_POWER_INPUT (U9.9), 02_10_POWER_INPUT (C92.1)
USB_BRIDGE_RESET_N: 16_Radar_service_USB_and_boot (U_USB.9), 17_Radar_service_USB_and_boot (R_USB_RESET.2)
USB_CTS_N: 16_Radar_service_USB_and_boot (U_USB.15), 17_Radar_service_USB_and_boot (R_USB_CTS.2)
USB_VBUS: 16_Radar_service_USB_and_boot (D_USB.4 JUSB1.1), 17_Radar_service_USB_and_boot (R_USB_VBUS_H.1)
USB_VBUS_SENSE: 16_Radar_service_USB_and_boot (U_USB.8), 17_Radar_service_USB_and_boot (R_USB_VBUS_H.2 R_USB_VBUS_L.1)
USB_WAKE_N: 16_Radar_service_USB_and_boot (U_USB.13), 17_Radar_service_USB_and_boot (R_USB_WAKE.2)
V12_SYS: 01_10_POWER_INPUT (10 pins), 02_10_POWER_INPUT (C1.1 C4.1 C90.1 C93.1), 03_10_POWER_INPUT (6 pins), 04_10_POWER_INPUT (R71.1 R800.1)
VCAP1_LOCAL: 09_20_MCU_CORE (U1.81), 10_20_MCU_CORE (C10.1)
VCAP2_LOCAL: 09_20_MCU_CORE (U1.125), 10_20_MCU_CORE (C11.1)
VDDA_FILTERED: 09_20_MCU_CORE (U1.38 U1.39), 10_20_MCU_CORE (C13.1 C14.1), 11_20_MCU_CORE (FB1.2)
VIN_PROTECTED_24V: 01_10_POWER_INPUT (5 pins), 02_10_POWER_INPUT (C800.1 C801.1 C802.1), 04_10_POWER_INPUT (R804.1 R806.2)
VIN_RAW: 01_10_POWER_INPUT (5 pins), 02_10_POWER_INPUT (C6I.1 Q7.2), 03_10_POWER_INPUT (D1.1), 04_10_POWER_INPUT (R61.1)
